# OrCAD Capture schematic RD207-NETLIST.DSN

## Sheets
1 8: size A3
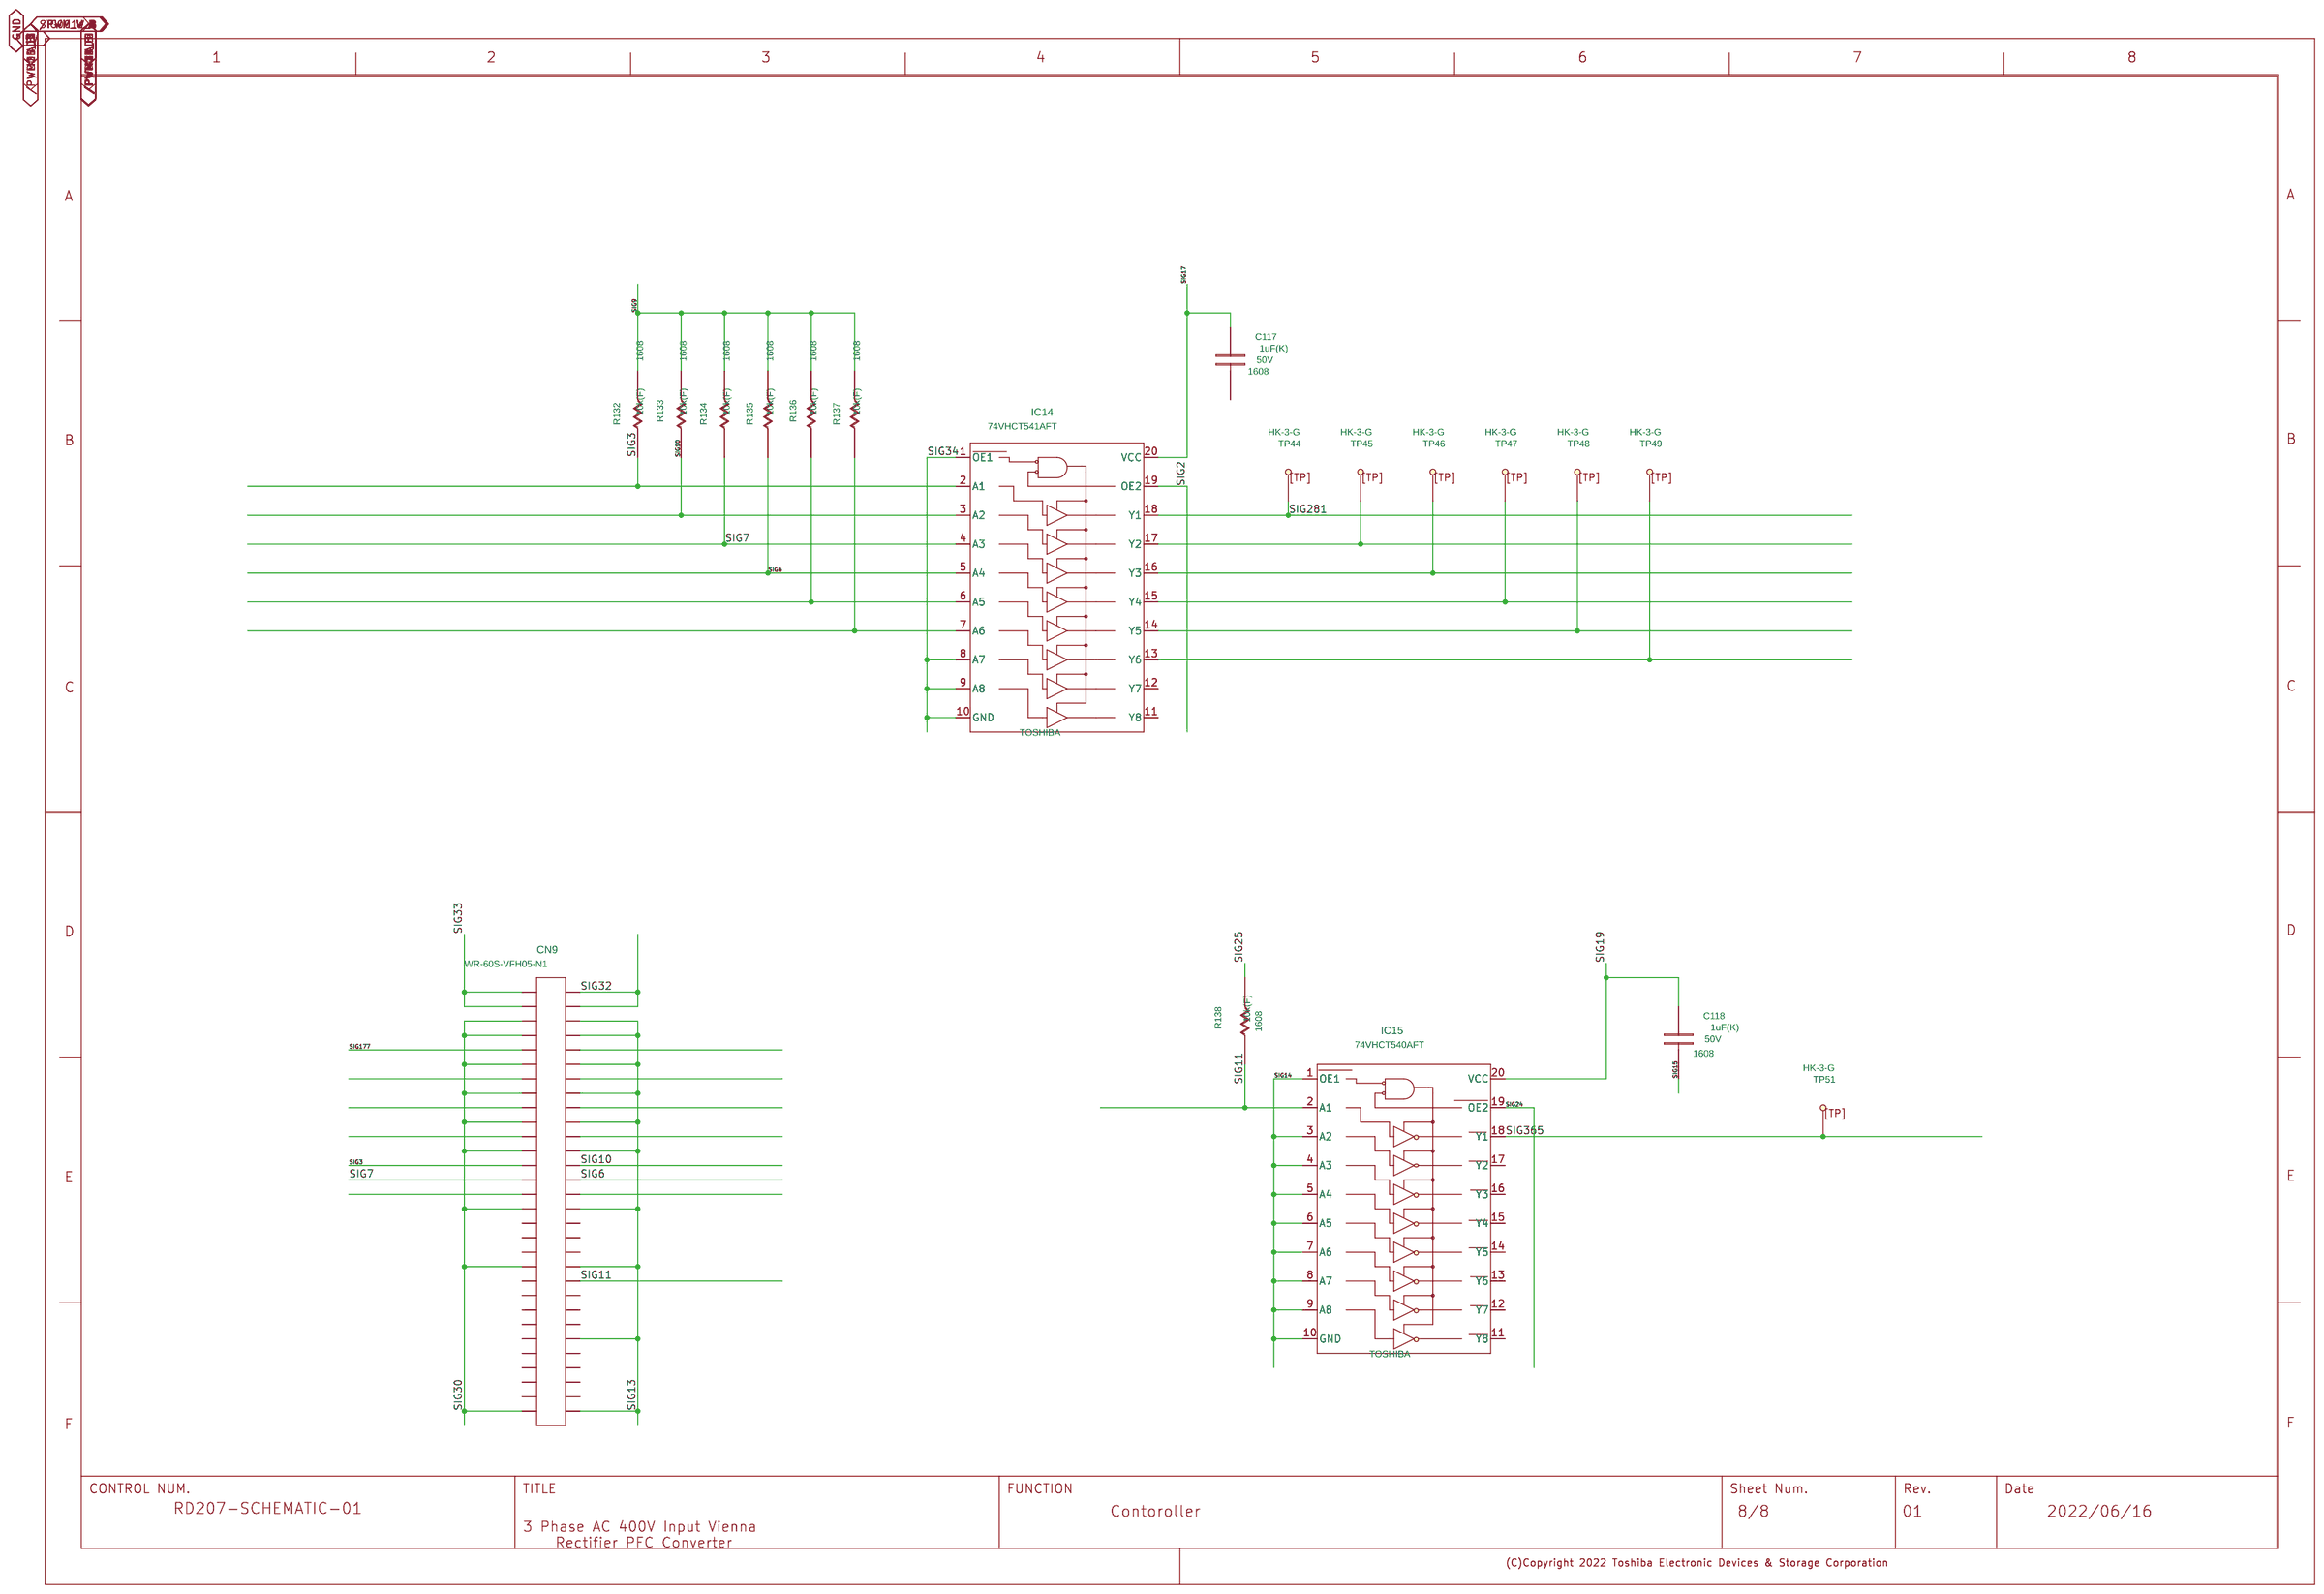
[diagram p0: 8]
2 7: size A3
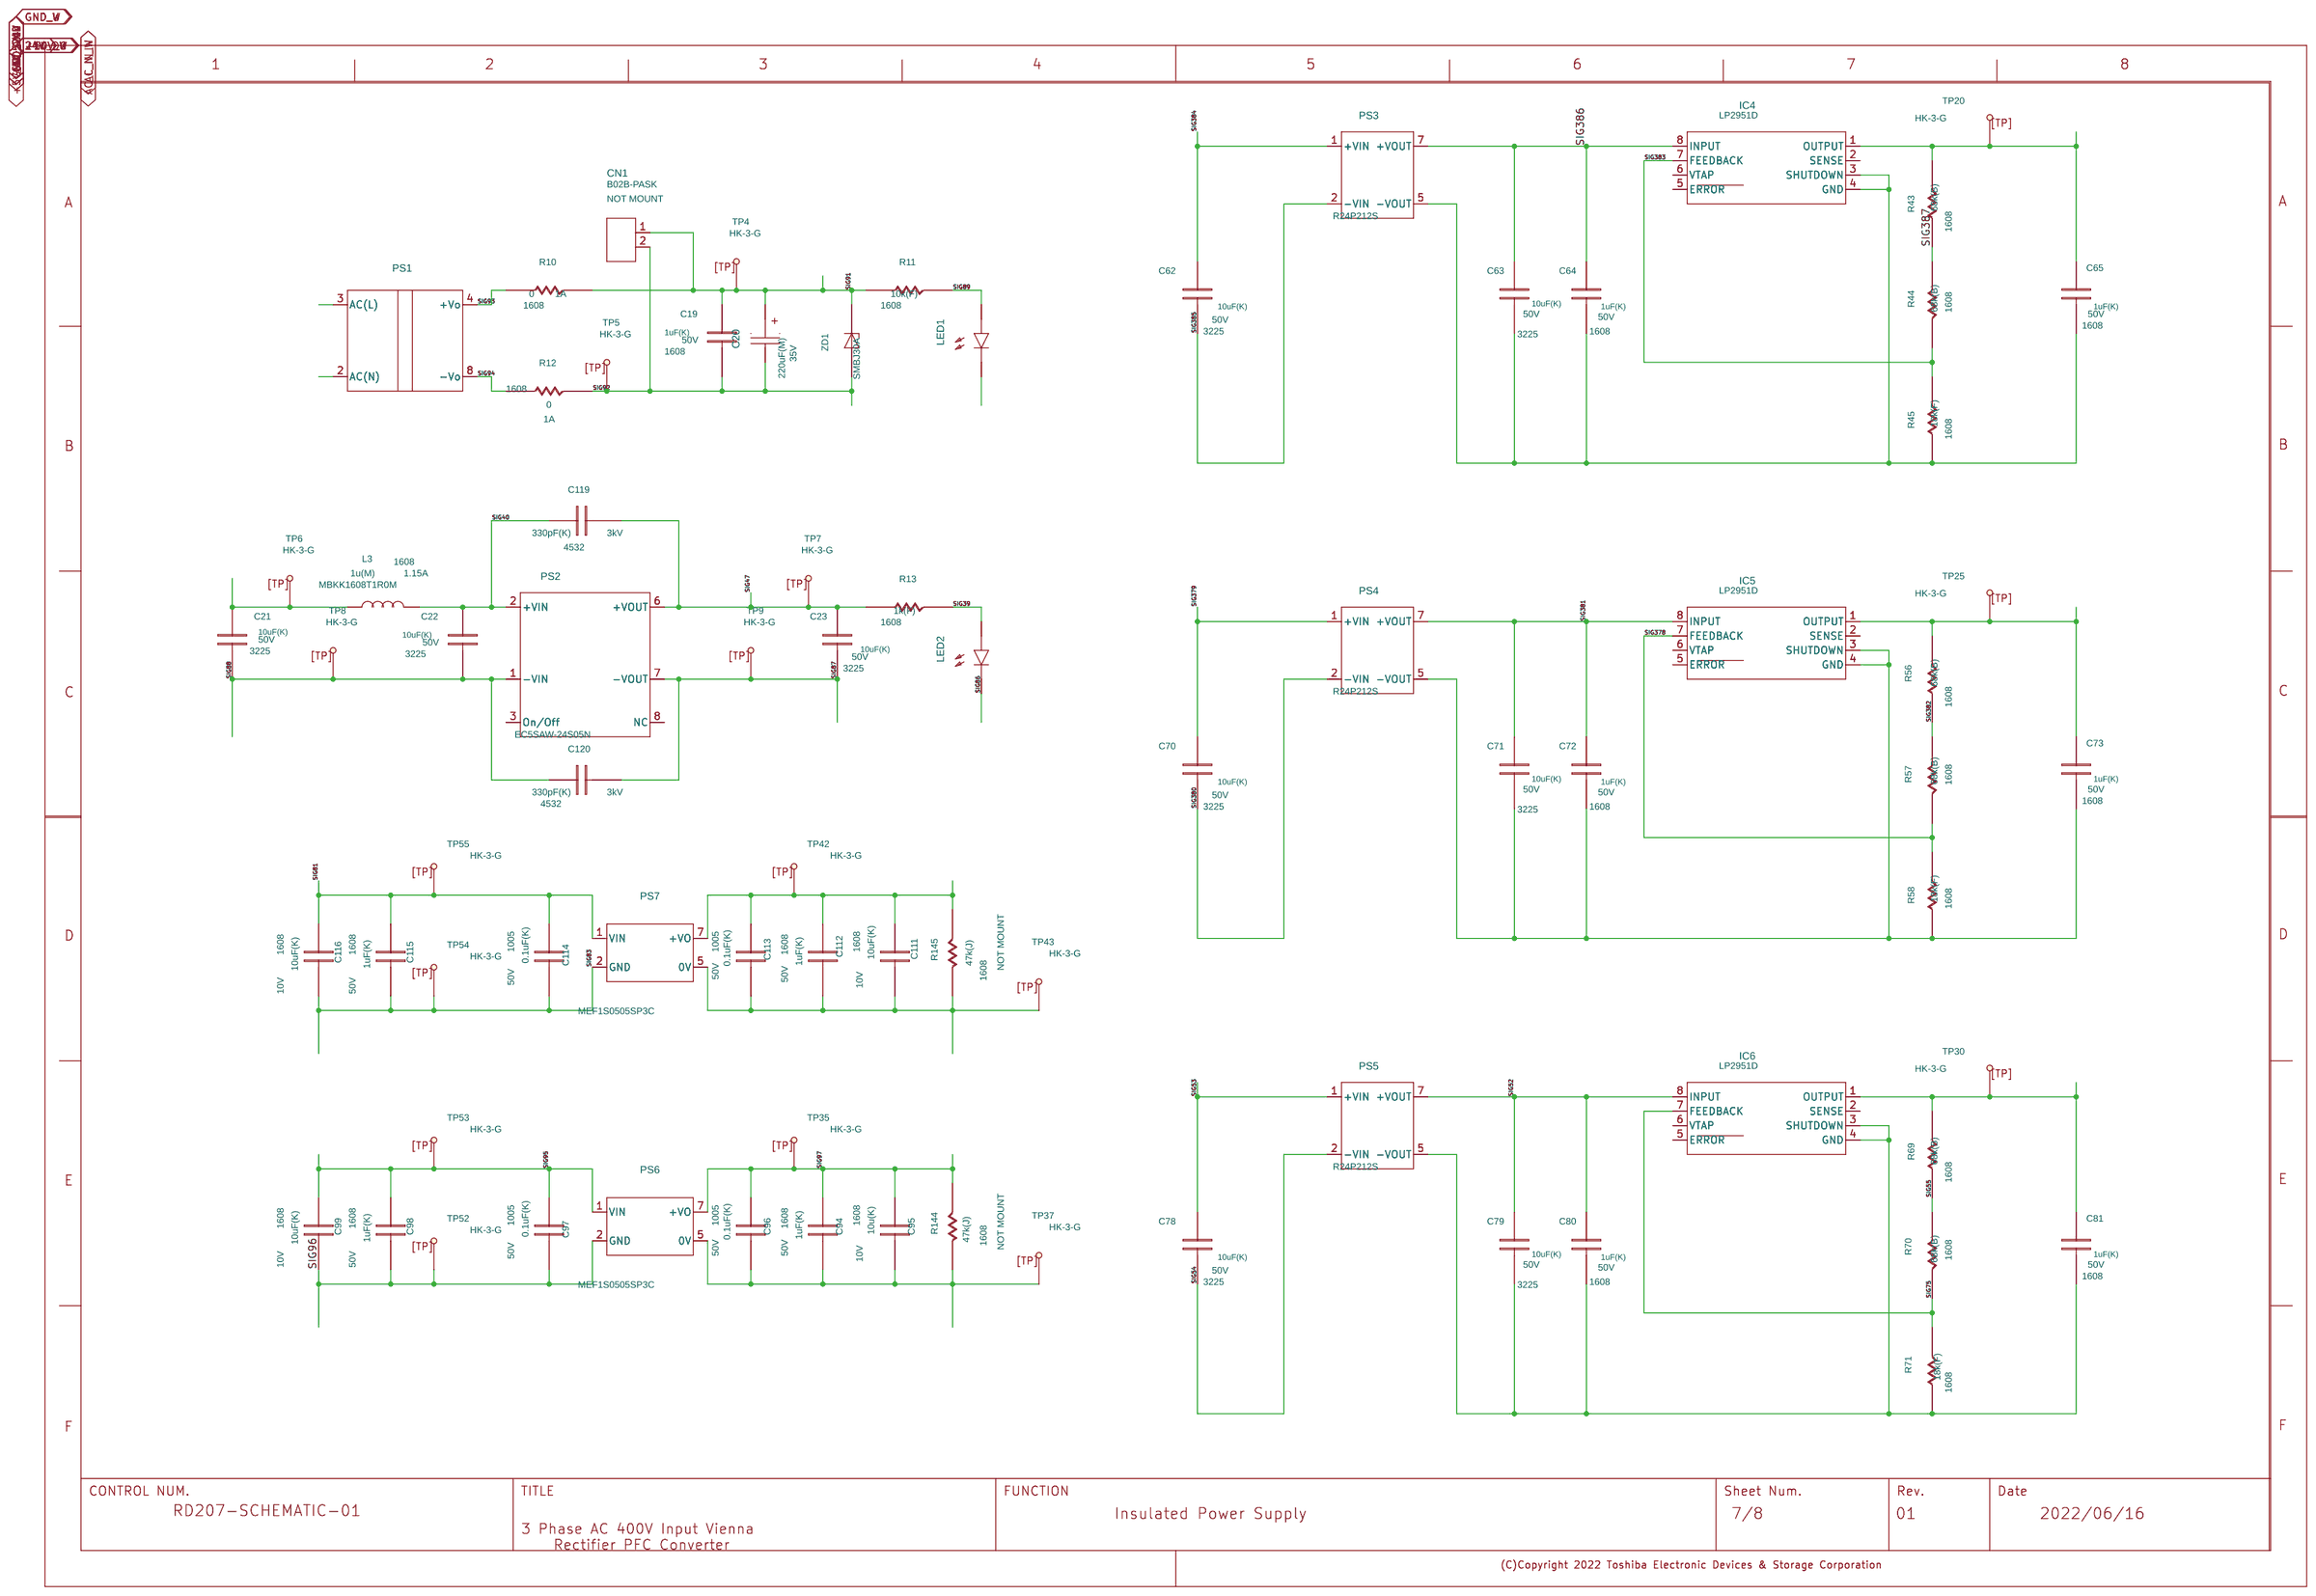
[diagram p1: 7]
3 6: size A3
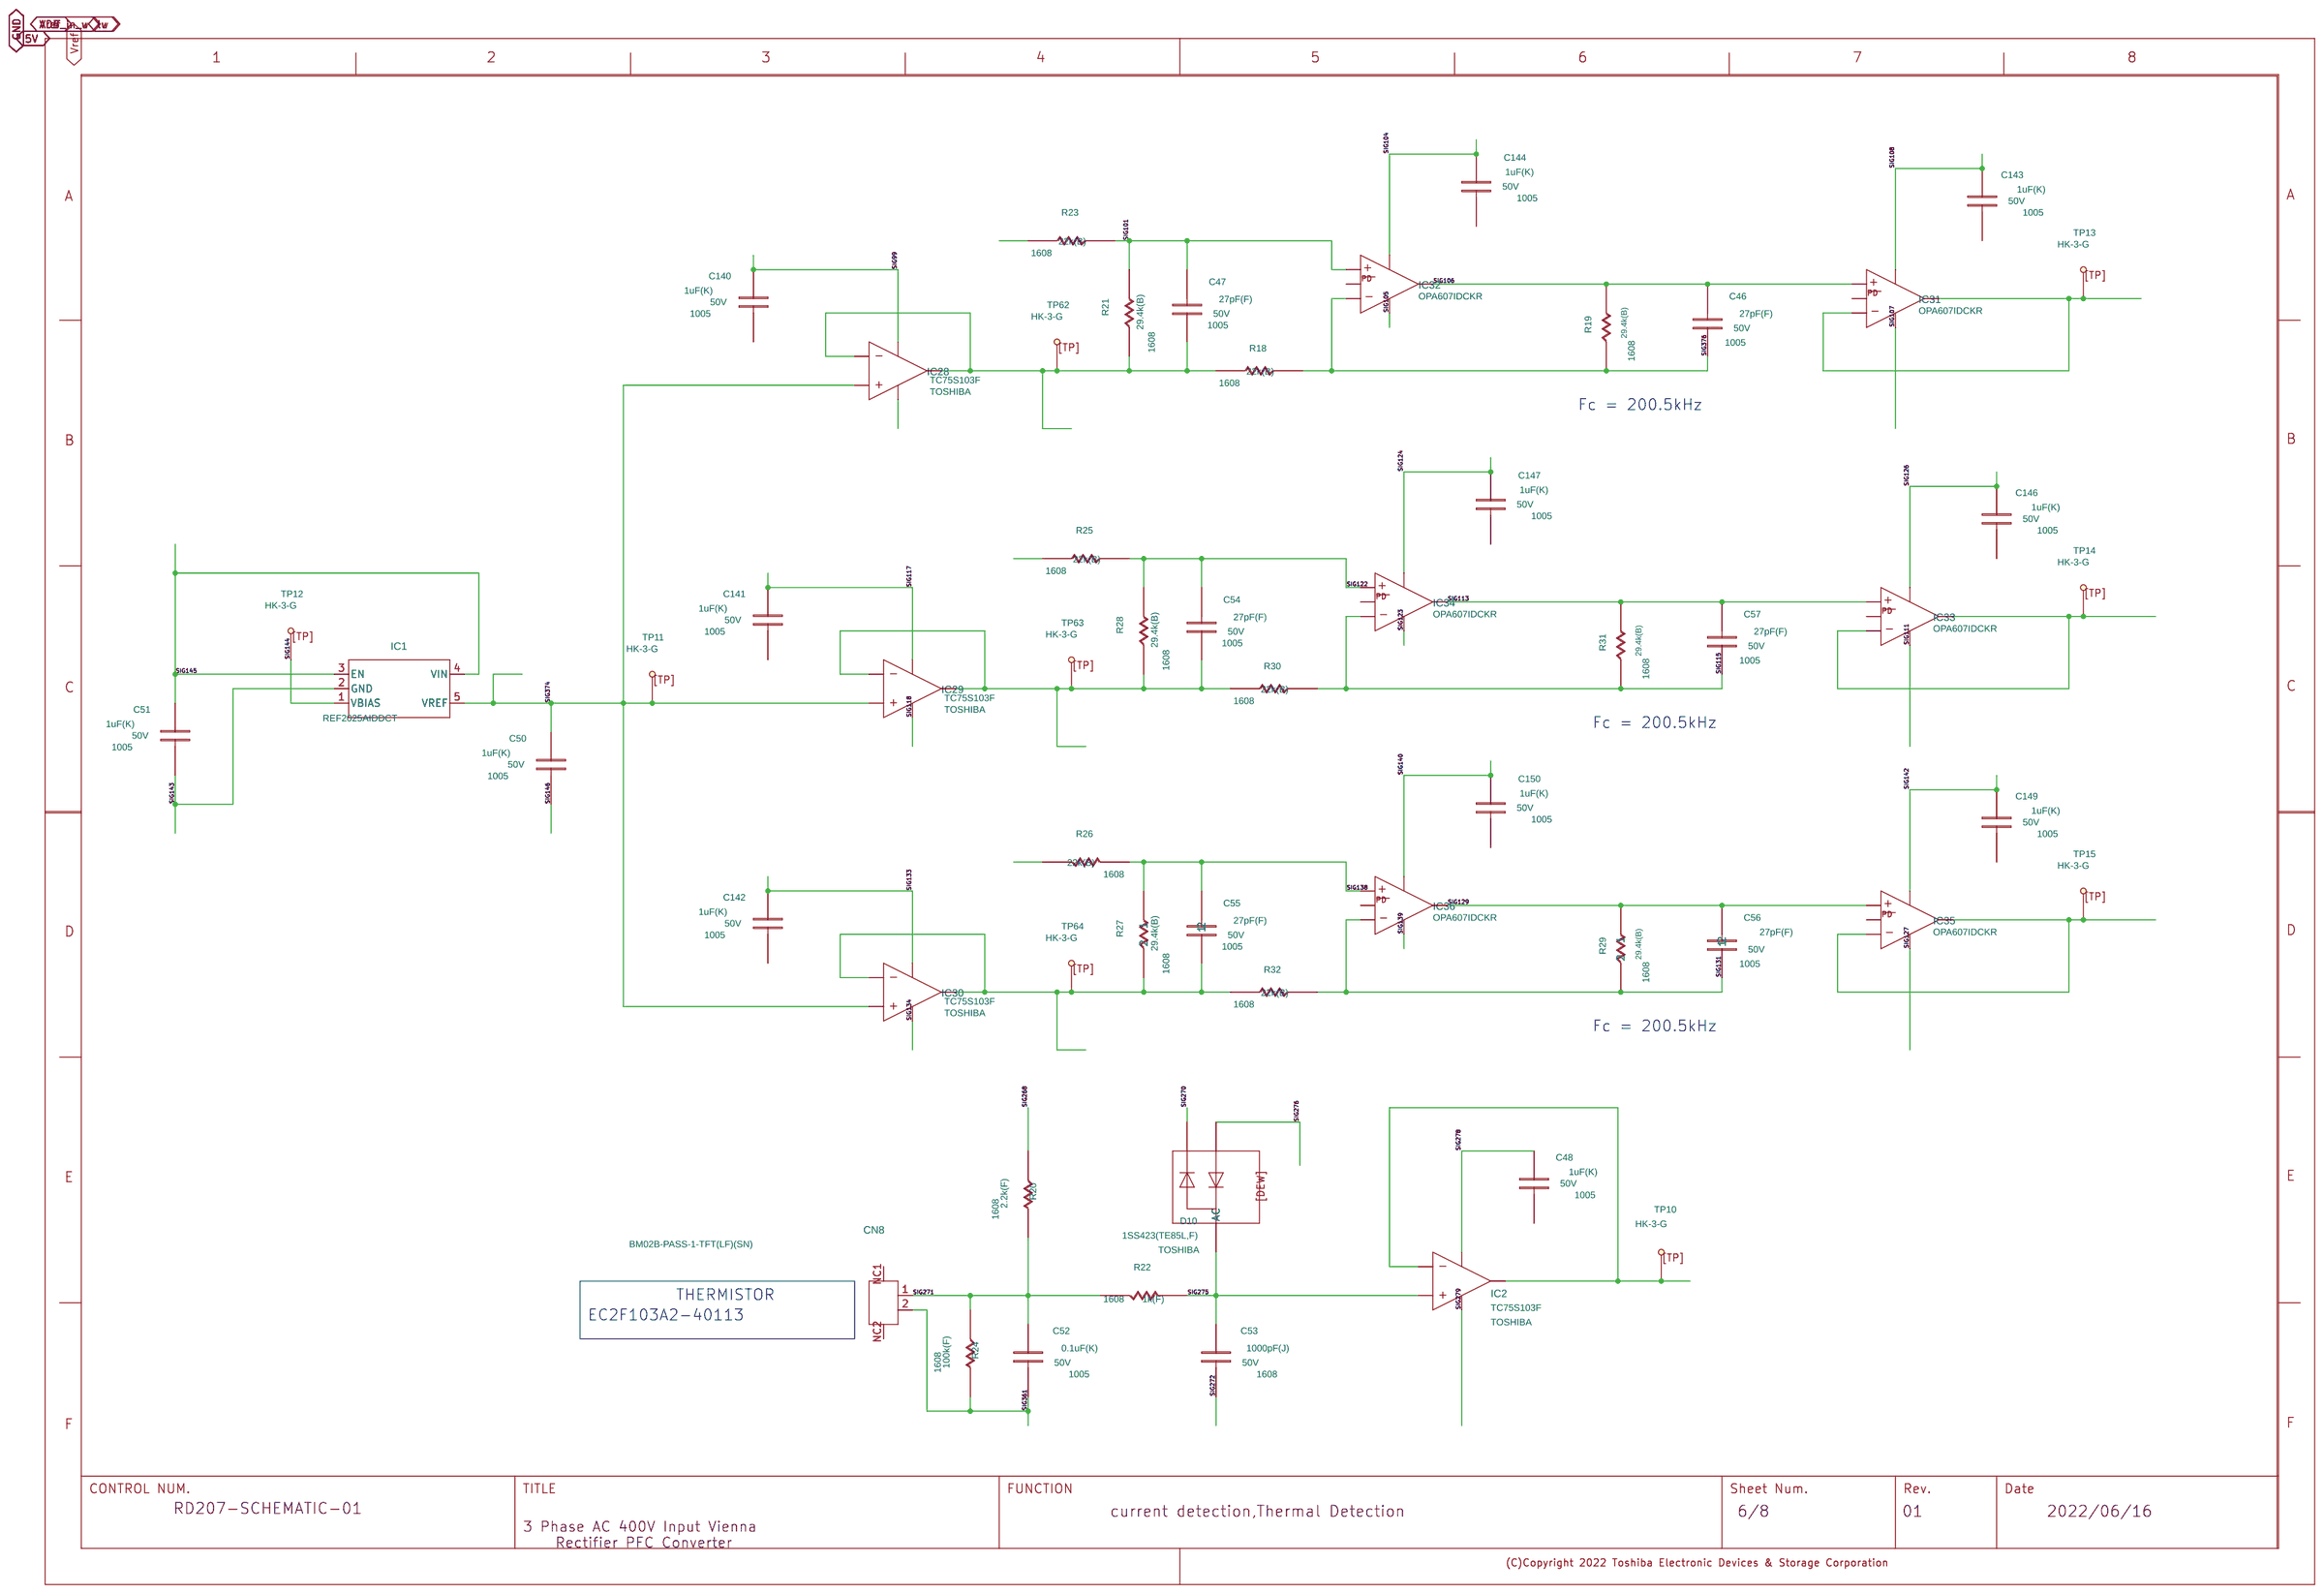
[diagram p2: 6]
4 5: size A3
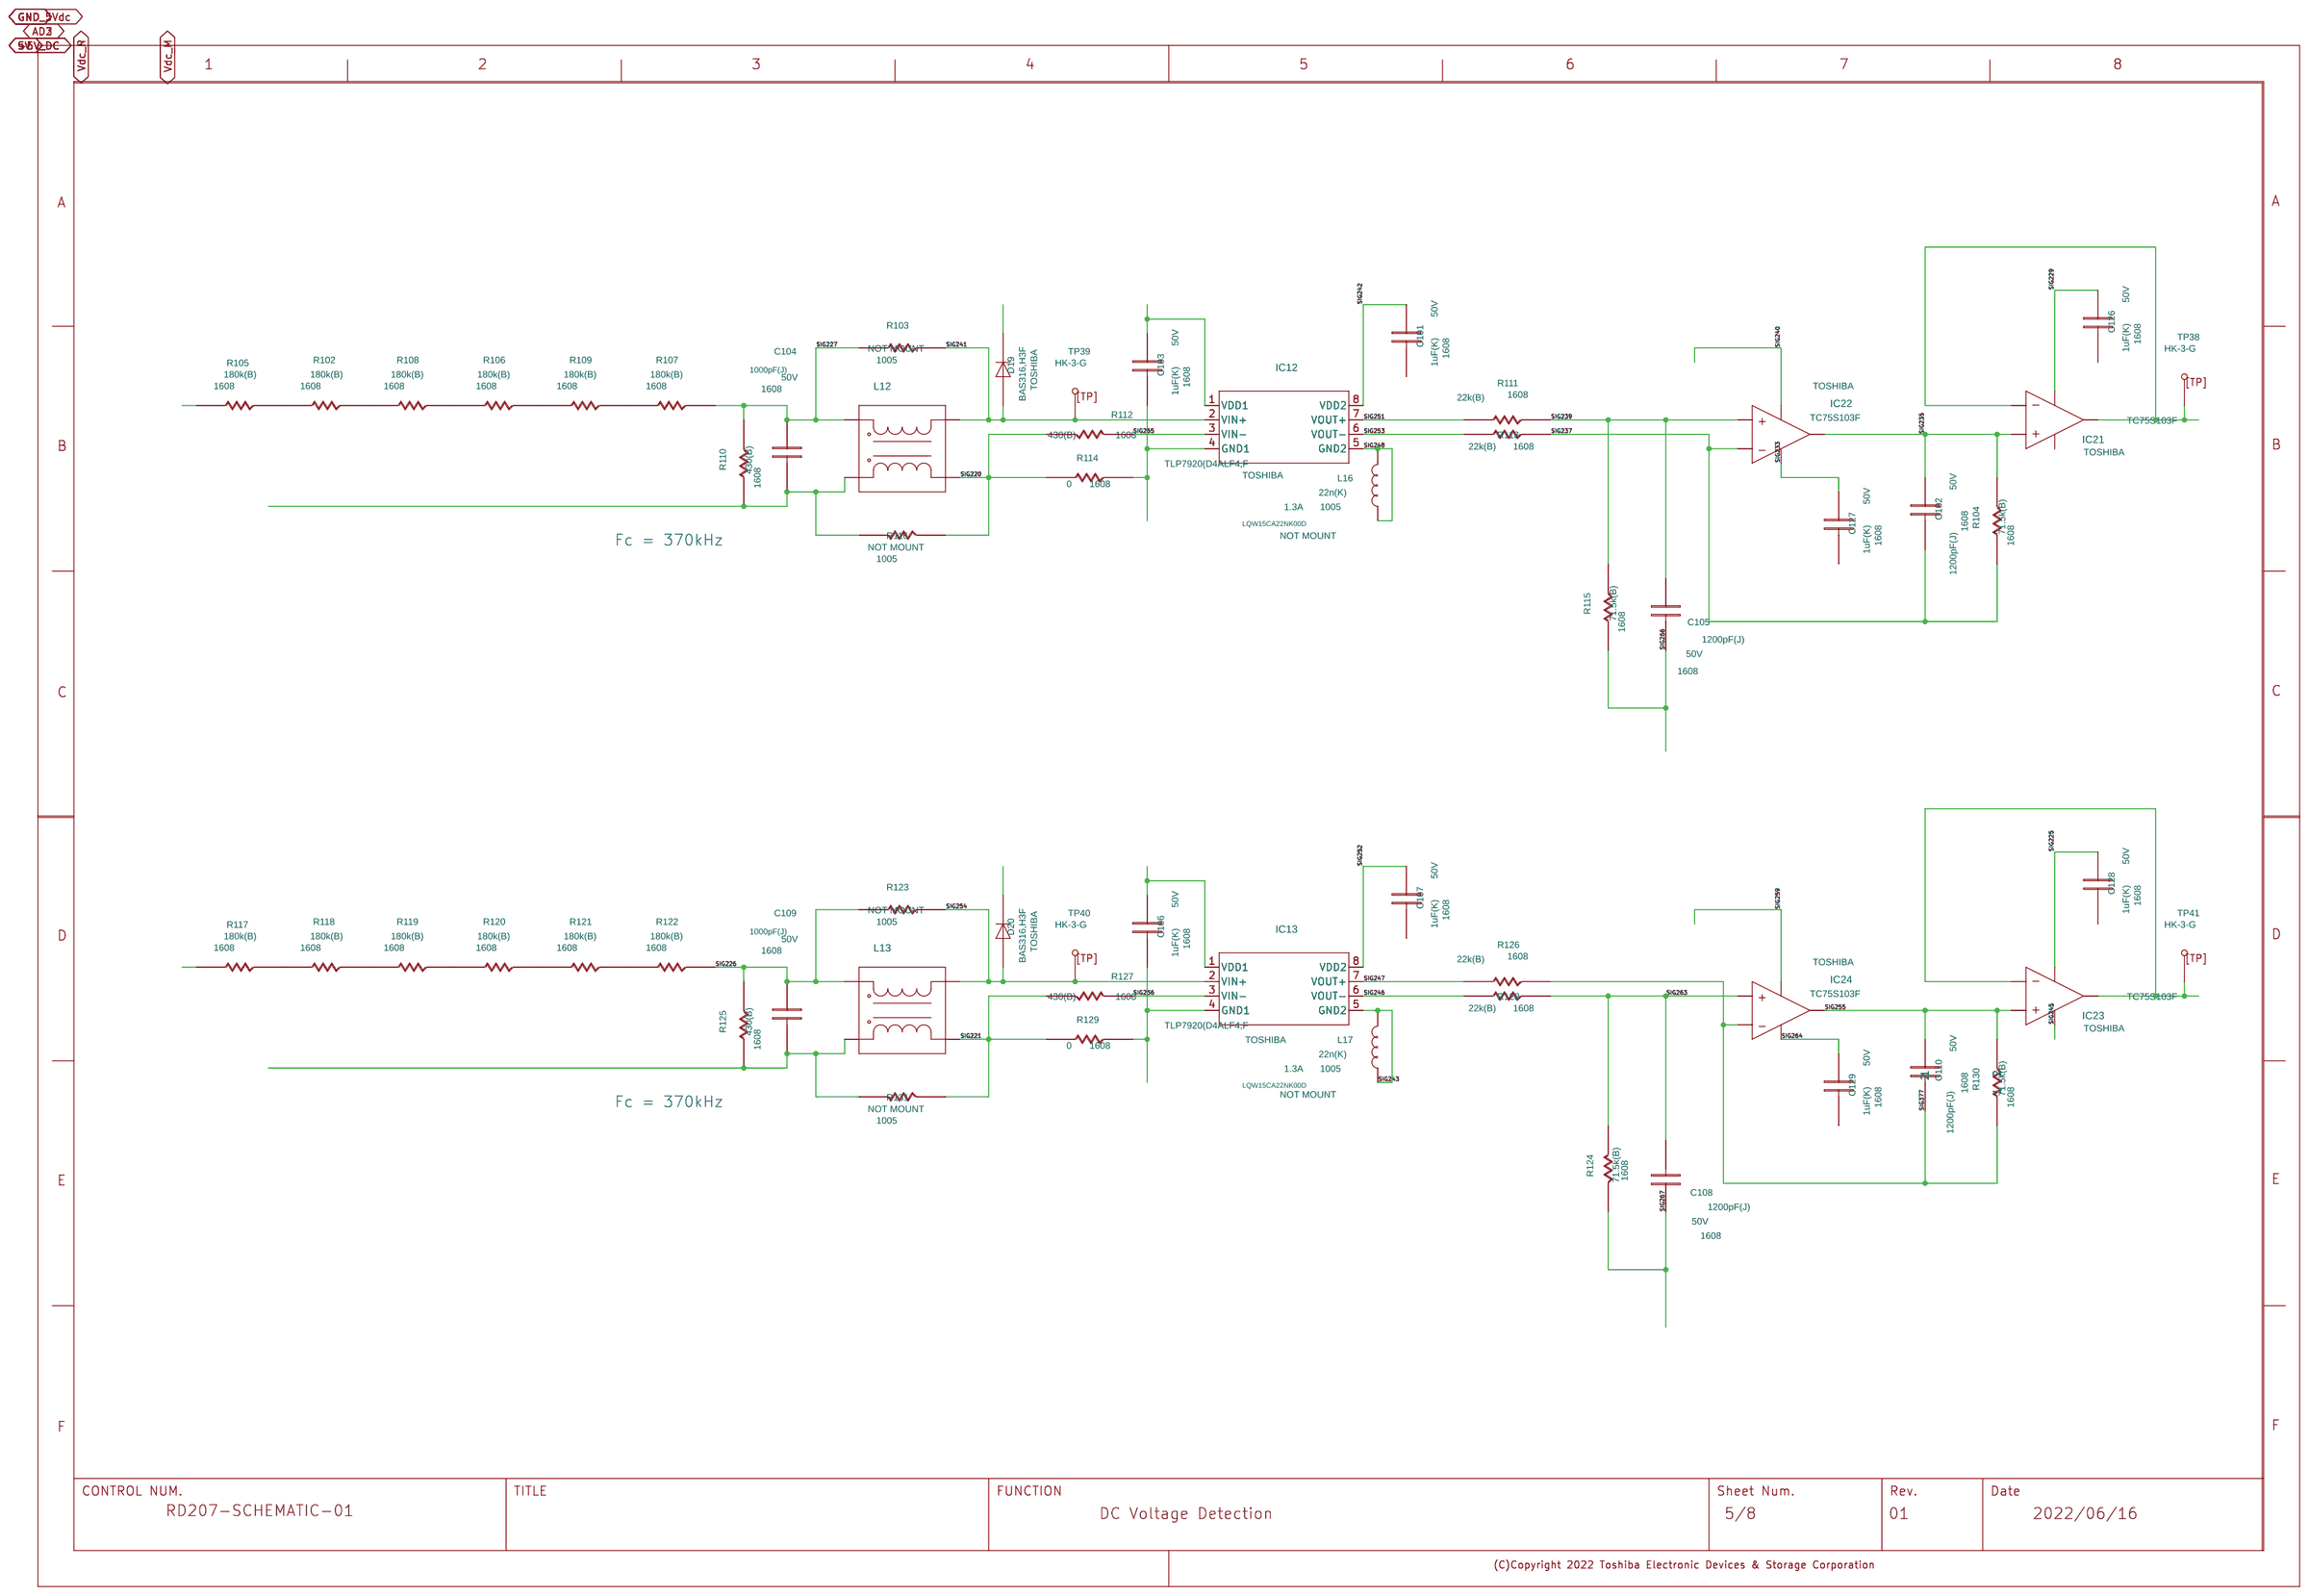
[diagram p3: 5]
5 4: size A3
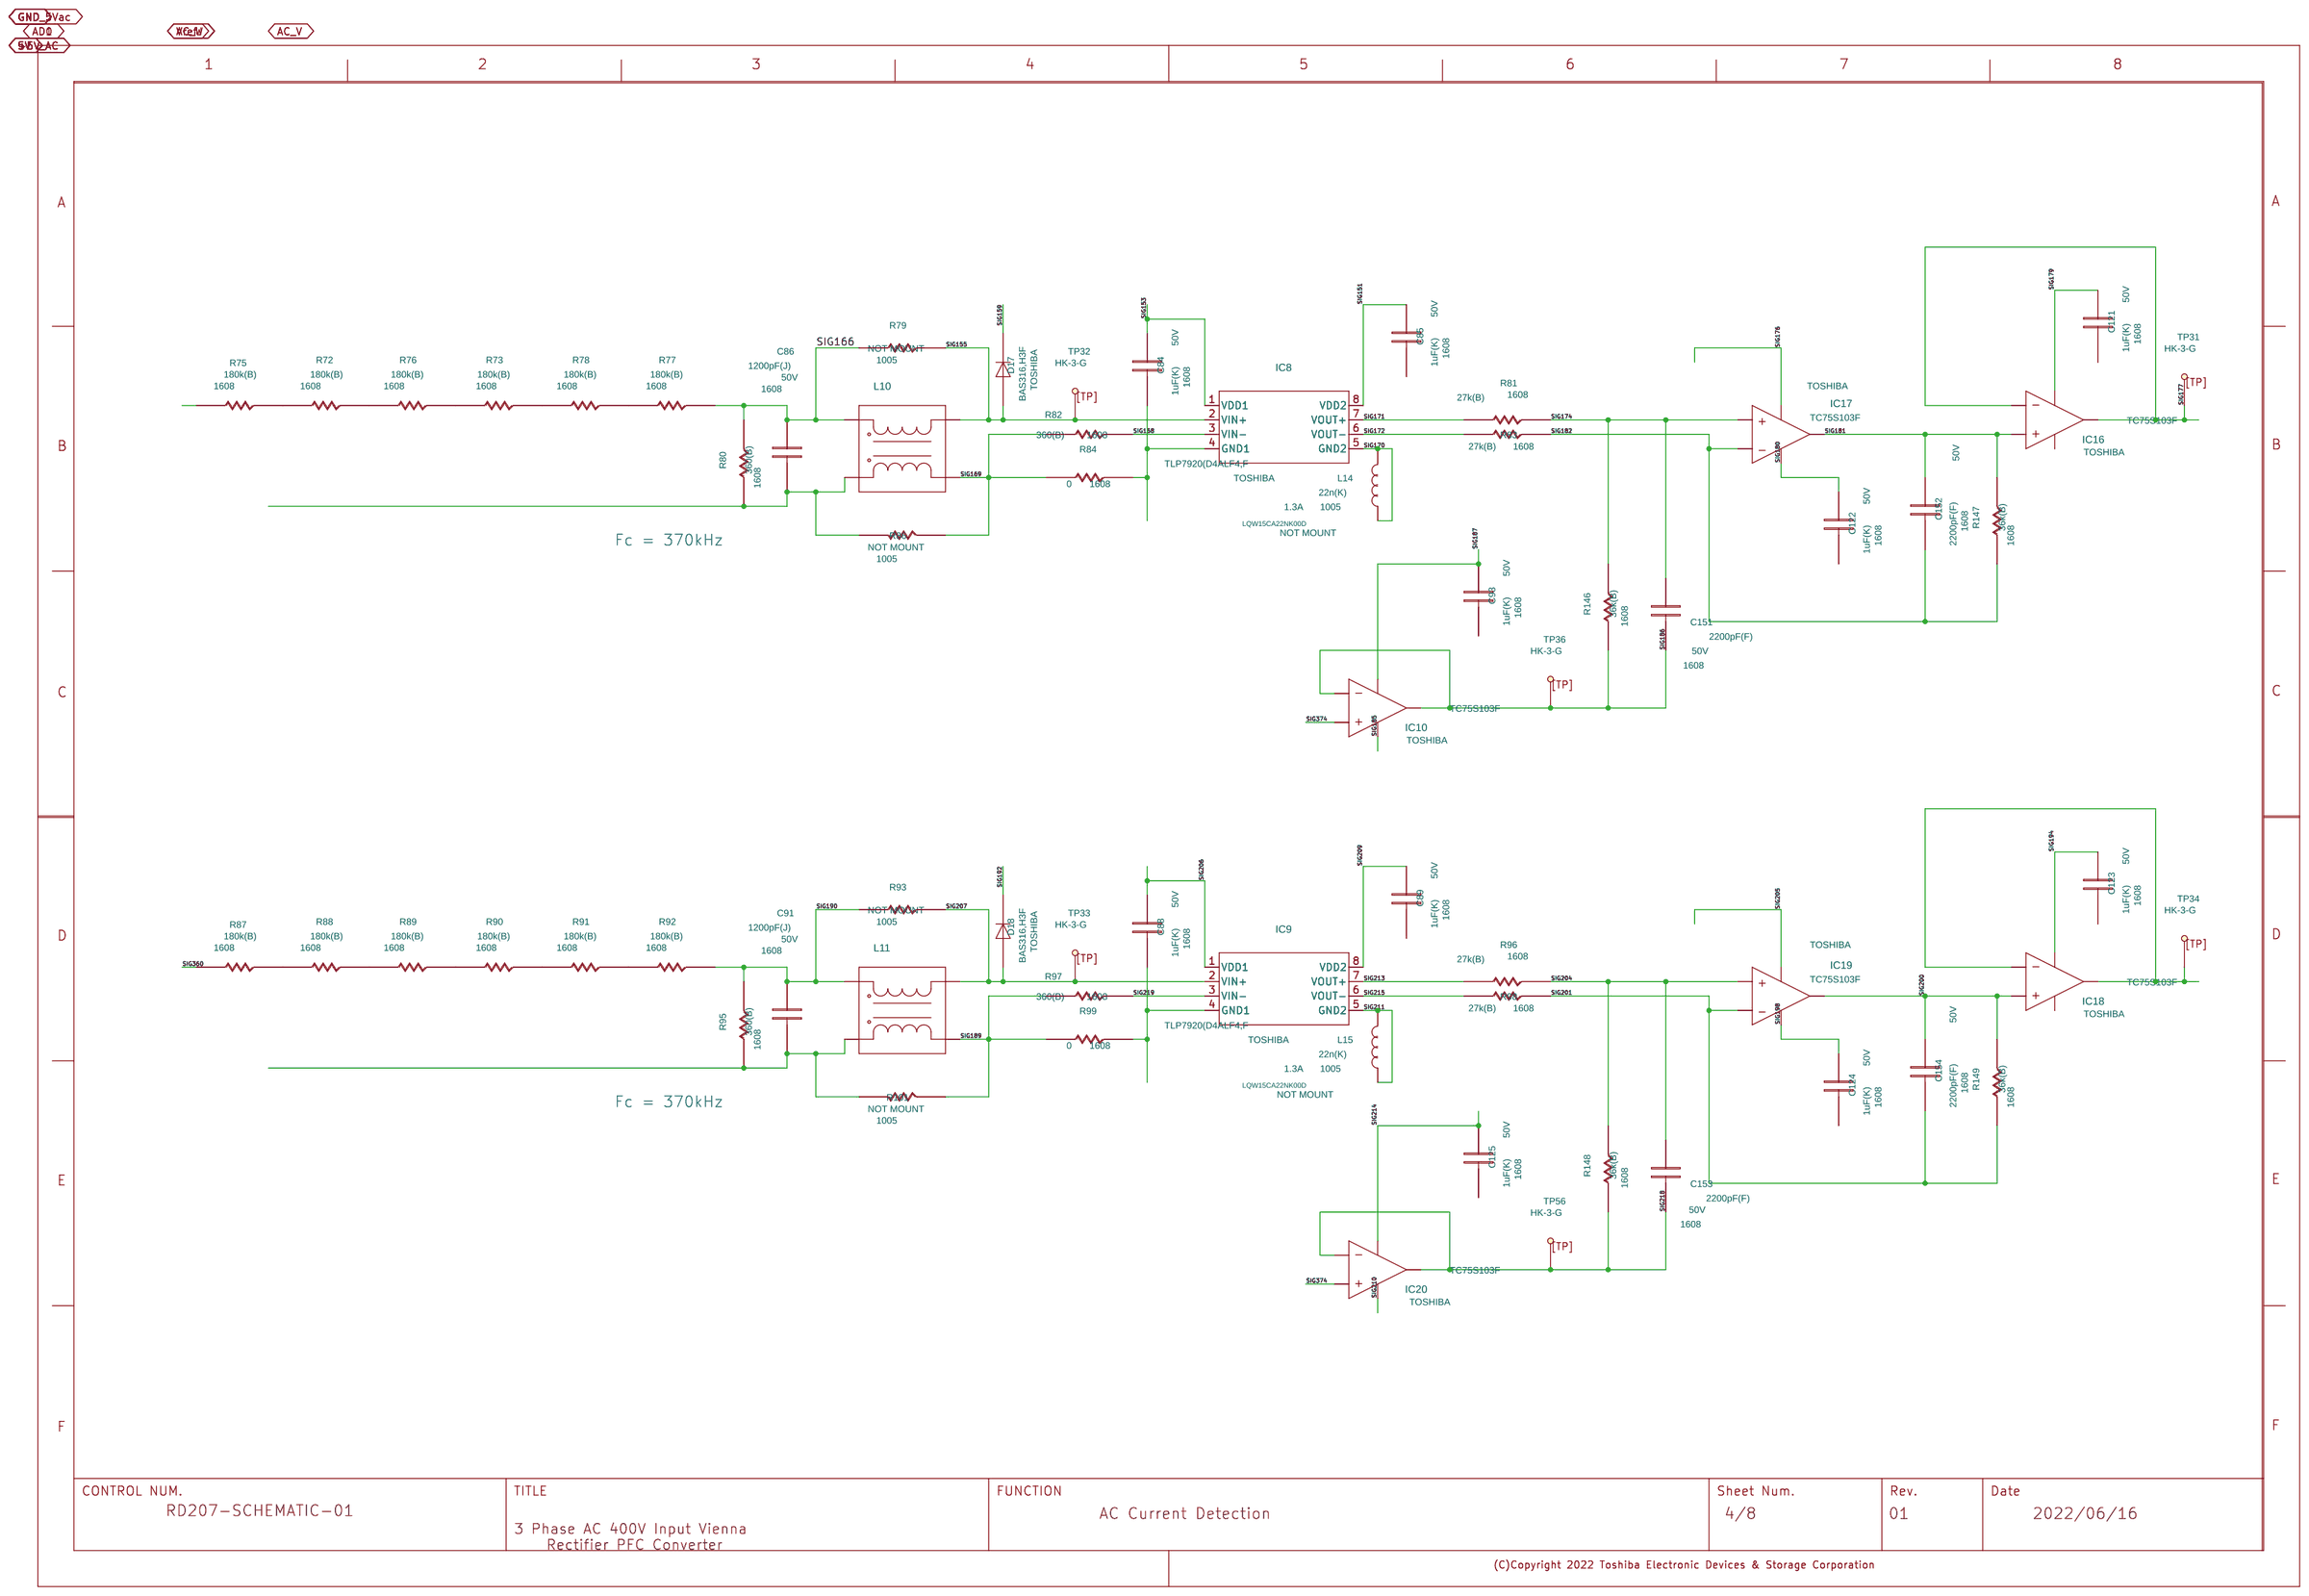
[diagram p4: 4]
6 3: size A3
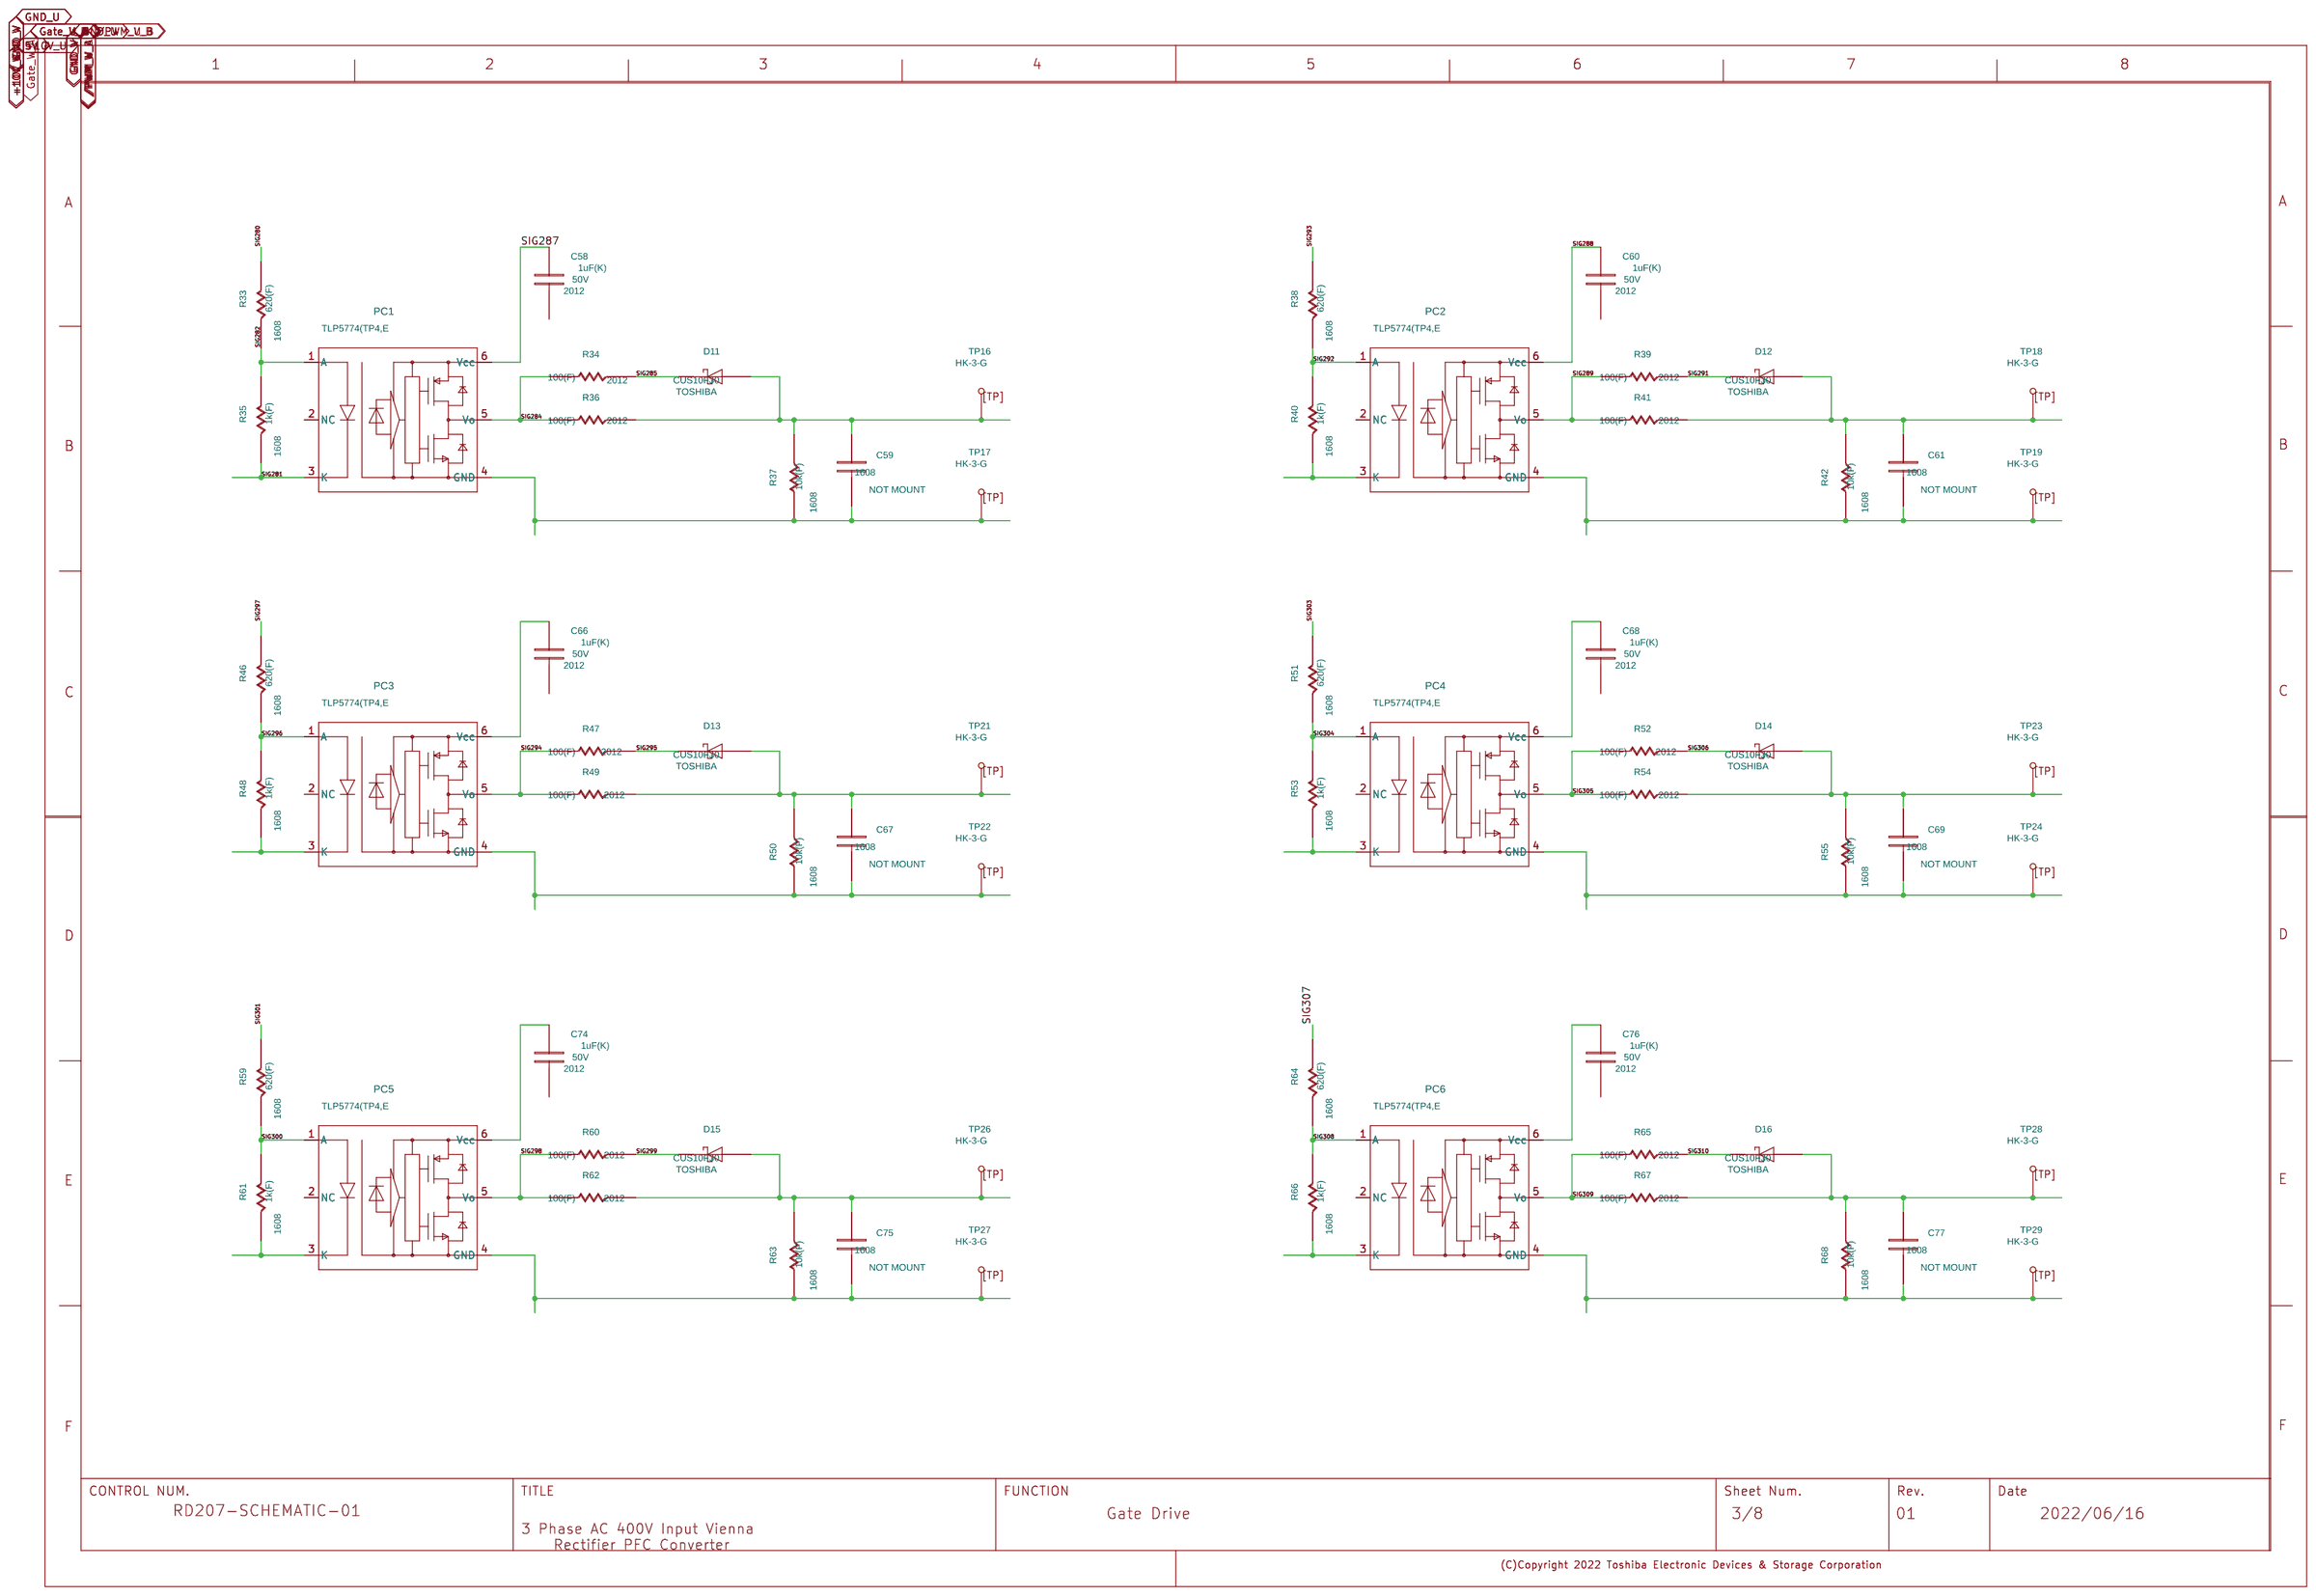
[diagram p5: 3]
7 2: size A3
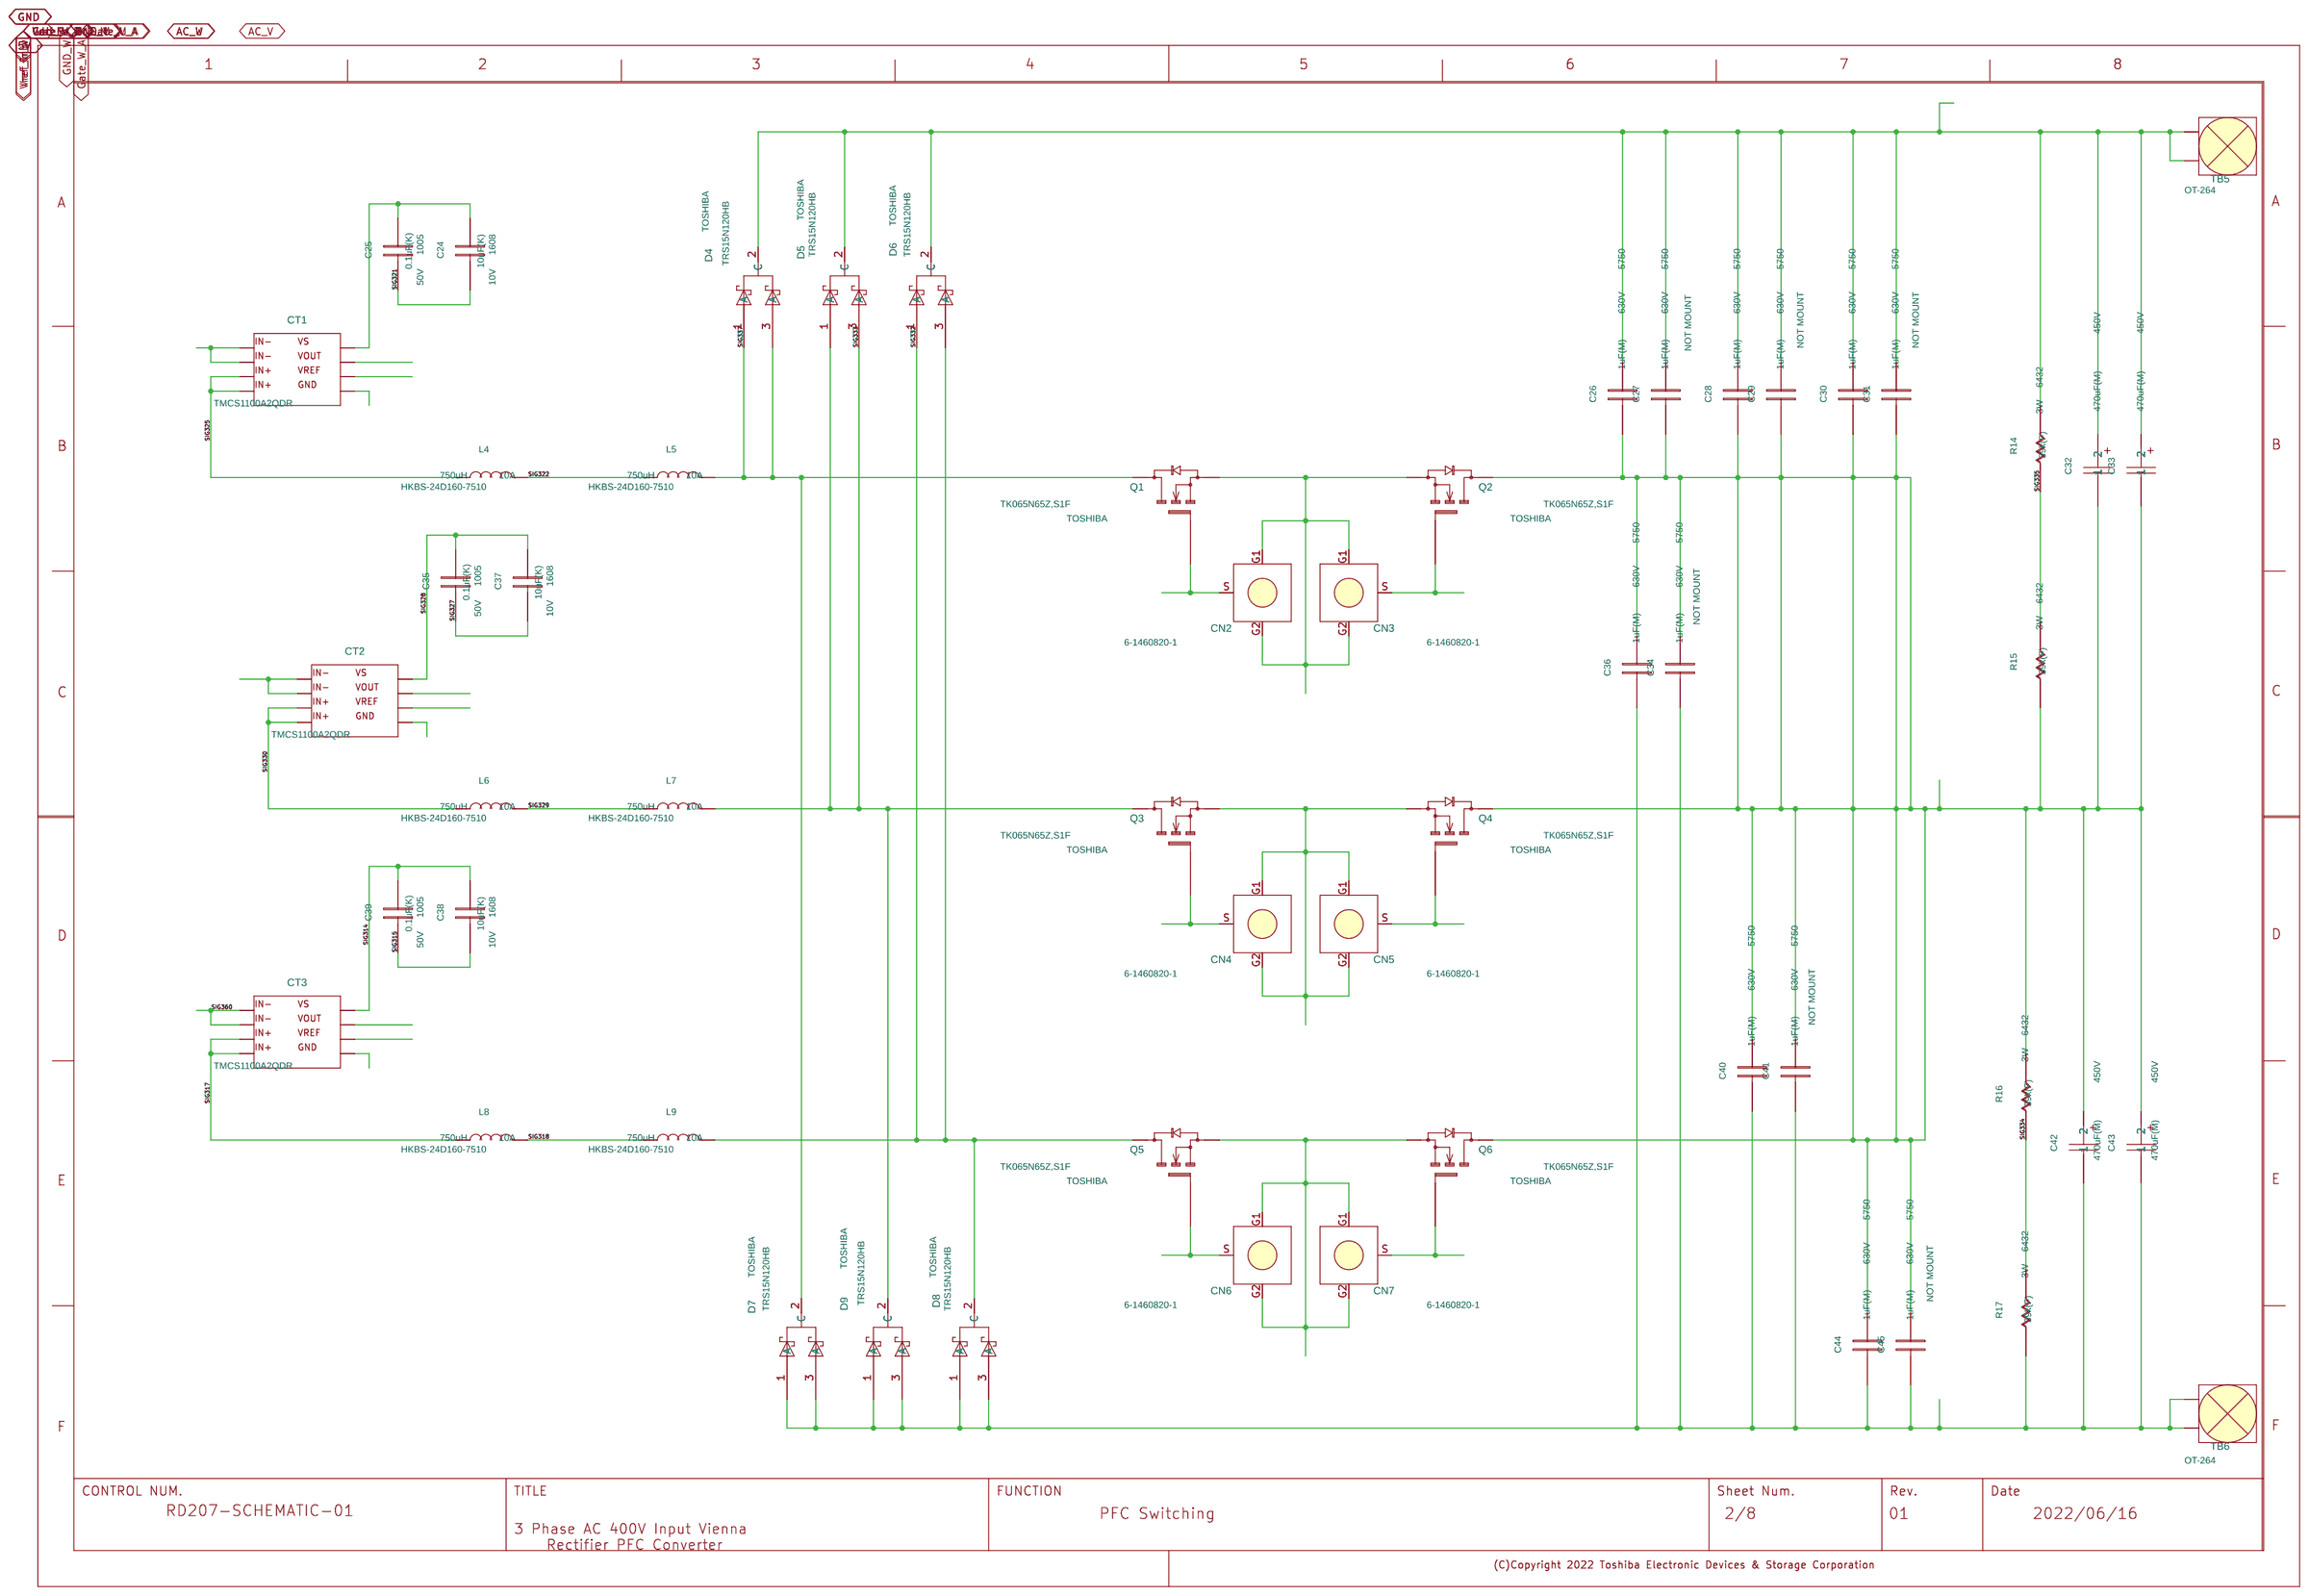
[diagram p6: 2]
8 1: size A3
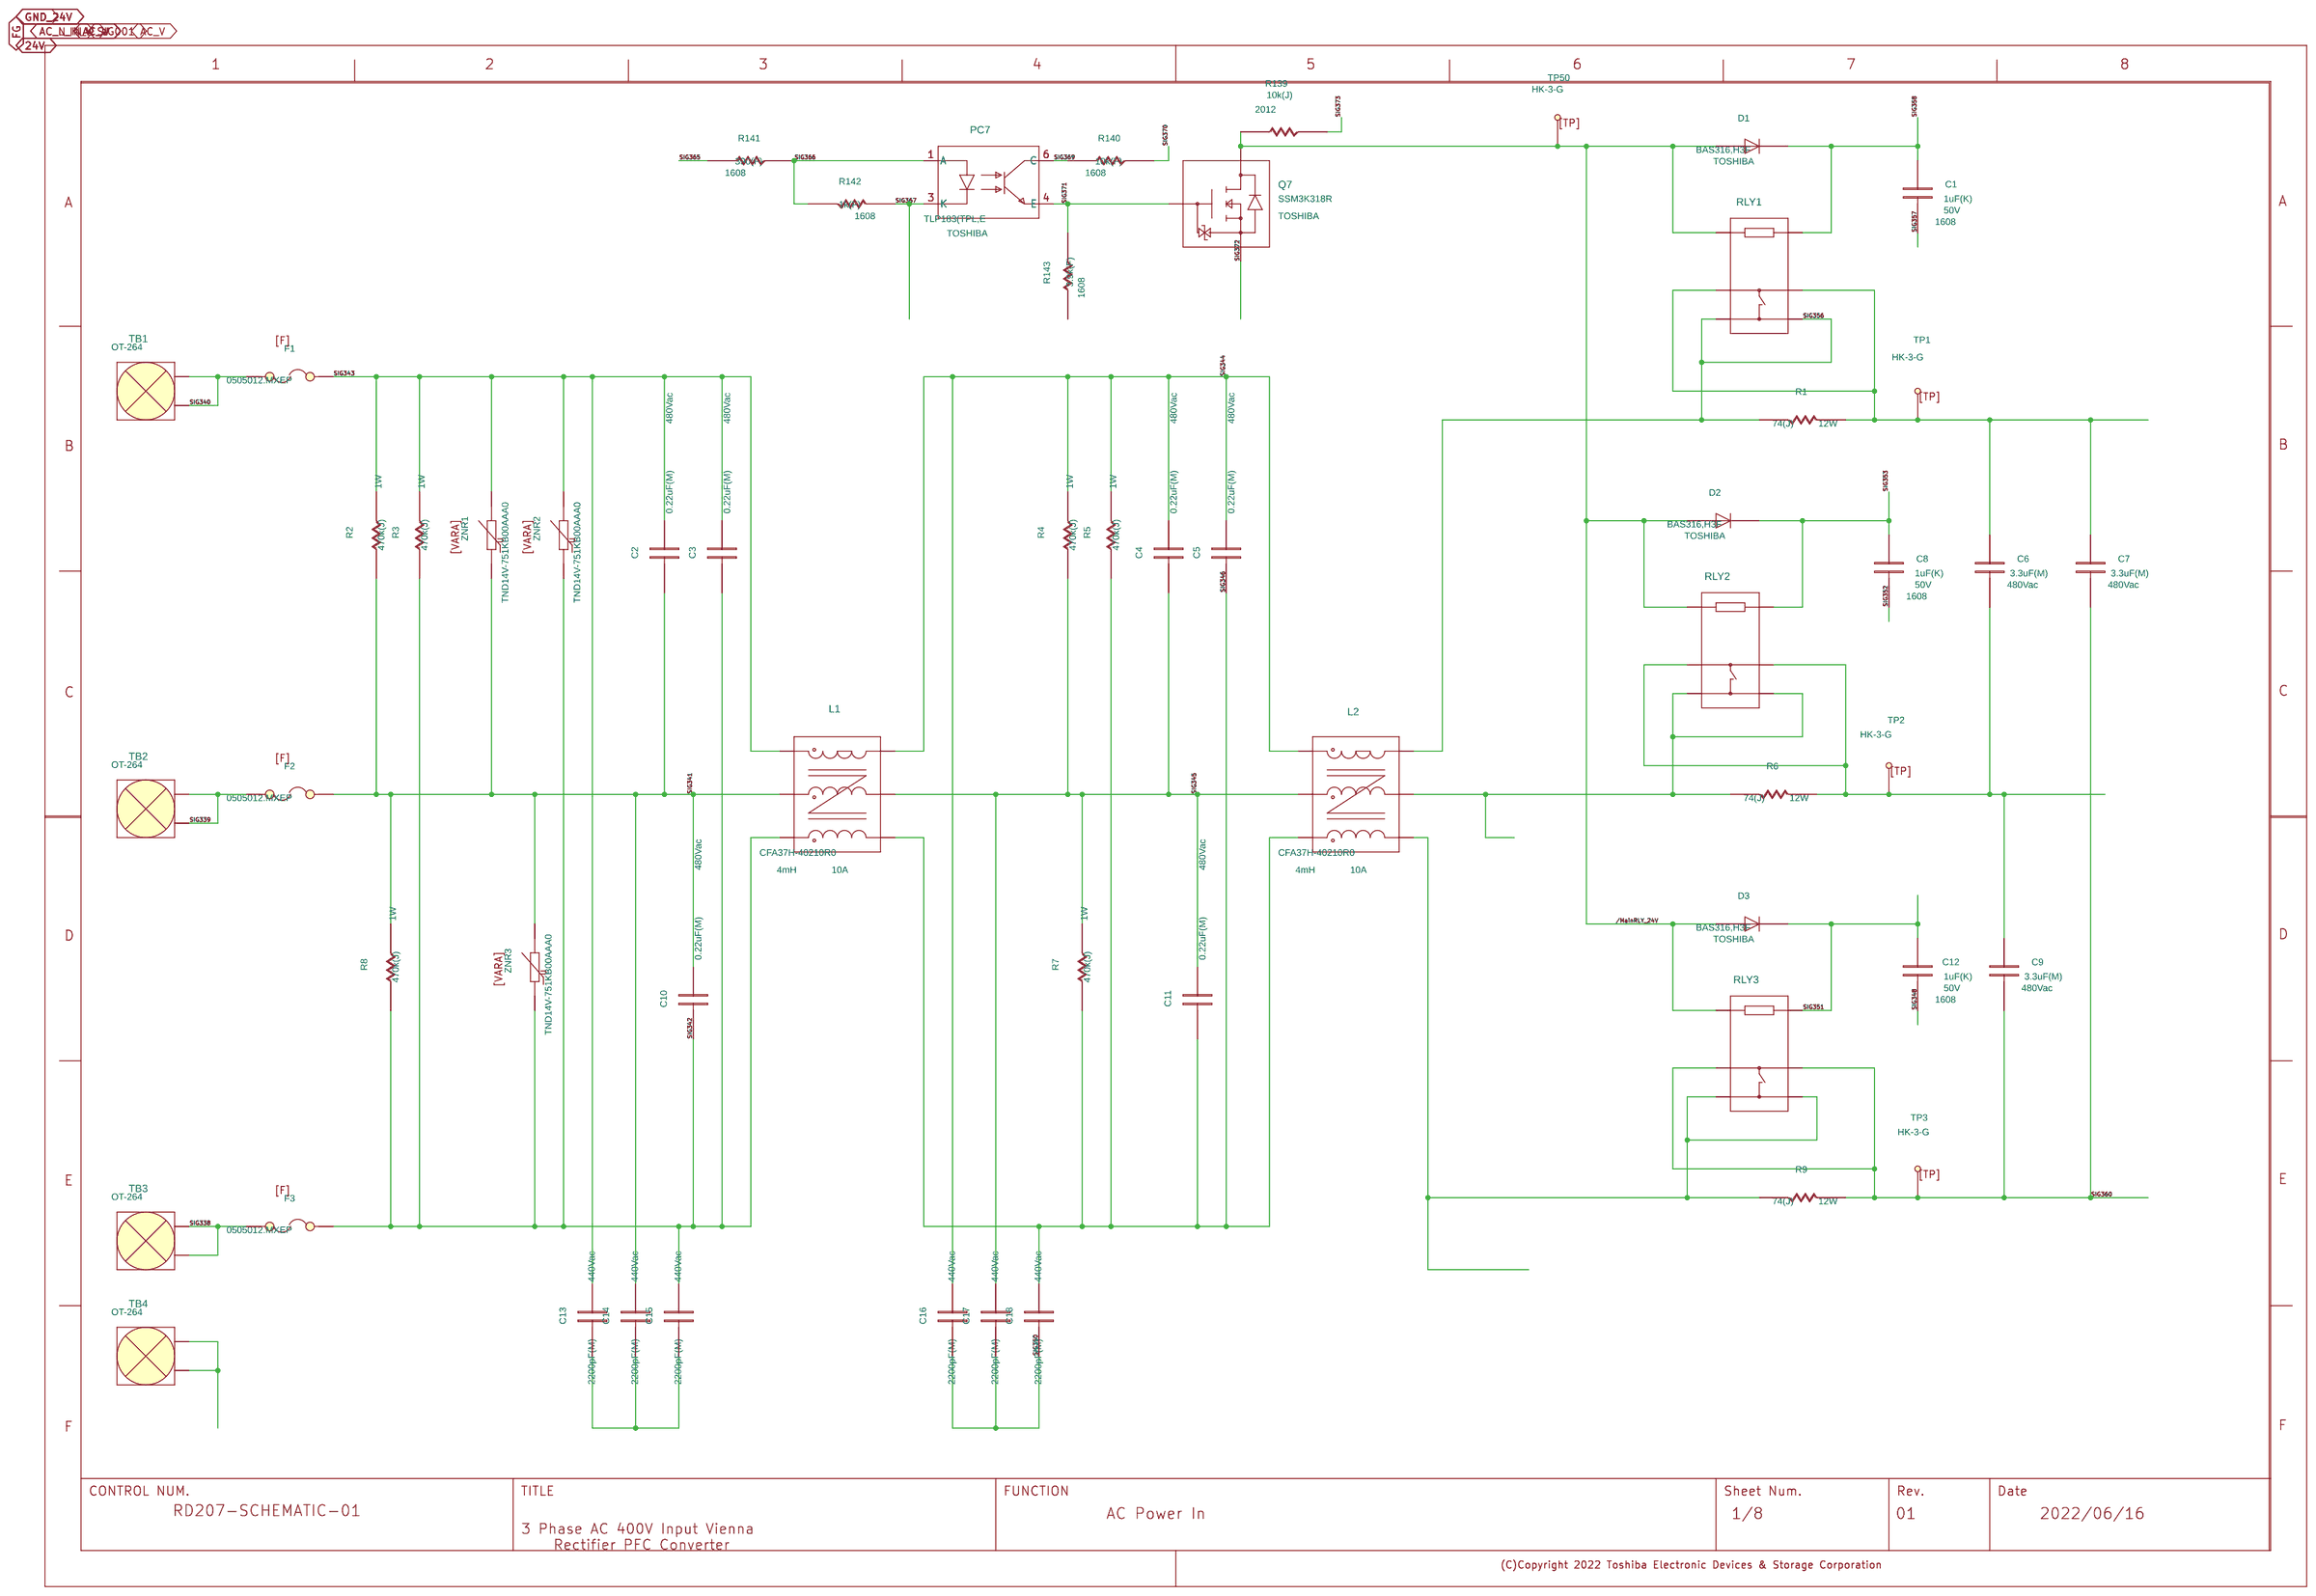
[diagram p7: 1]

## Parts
sheet 1
C1  C
C2  C
C3  C
C4  C
C5  C
C6  C
C7  C
C8  C
C9  C
C10  C
C11  C
C12  C
C13  C
C14  C
C15  C
C16  C
C17  C
C18  C
D1  D
D2  D
D3  D
F1  F
F2  F
F3  F
L1  CFA37H-40210R0
L2  CFA37H-40210R0
PC7  TLP183(TPL,E
Q7  SSM3K318R
R1  R
R2  R
R3  R
R4  R
R5  R
R6  R
R7  R
R8  R
R9  R
R139  R
R140  R
R141  R
R142  R
R143  R
RLY1  G2RL-1A4-E-CF DC24
RLY2  G2RL-1A4-E-CF DC24
RLY3  G2RL-1A4-E-CF DC24
TB1  OT-264
TB2  OT-264
TB3  OT-264
TB4  OT-264
TP1  TP
TP2  TP
TP3  TP
TP50  TP
U?#7  WAKU_DEF100
ZNR1  VARA
ZNR2  VARA
ZNR3  VARA
sheet 2
C24  C
C25  C
C26  C
C27  C
C28  C
C29  C
C30  C
C31  C
C32  CP
C33  CP
C34  C
C35  C
C36  C
C37  C
C38  C
C39  C
C40  C
C41  C
C42  CP
C43  CP
C44  C
C45  C
CN2  6-1460820-1
CN3  6-1460820-1
CN4  6-1460820-1
CN5  6-1460820-1
CN6  6-1460820-1
CN7  6-1460820-1
CT1  TMCS1100A2QDR
CT2  TMCS1100A2QDR
CT3  TMCS1100A2QDR
D4  TRS15N120HB
D5  TRS15N120HB
D6  TRS15N120HB
D7  TRS15N120HB
D8  TRS15N120HB
D9  TRS15N120HB
L4  L
L5  L
L6  L
L7  L
L8  L
L9  L
Q1  TK065N65Z,S1F
Q2  TK065N65Z,S1F
Q3  TK065N65Z,S1F
Q4  TK065N65Z,S1F
Q5  TK065N65Z,S1F
Q6  TK065N65Z,S1F
R14  R
R15  R
R16  R
R17  R
TB5  OT-264
TB6  OT-264
U?#6  WAKU_DEF100
sheet 3
C58  C
C59  C
C60  C
C61  C
C66  C
C67  C
C68  C
C69  C
C74  C
C75  C
C76  C
C77  C
D11  SBD
D12  SBD
D13  SBD
D14  SBD
D15  SBD
D16  SBD
PC1  TLP5774
PC2  TLP5774
PC3  TLP5774
PC4  TLP5774
PC5  TLP5774
PC6  TLP5774
R33  R
R34  R
R35  R
R36  R
R37  R
R38  R
R39  R
R40  R
R41  R
R42  R
R46  R
R47  R
R48  R
R49  R
R50  R
R51  R
R52  R
R53  R
R54  R
R55  R
R59  R
R60  R
R61  R
R62  R
R63  R
R64  R
R65  R
R66  R
R67  R
R68  R
TP16  TP
TP17  TP
TP18  TP
TP19  TP
TP21  TP
TP22  TP
TP23  TP
TP24  TP
TP26  TP
TP27  TP
TP28  TP
TP29  TP
U?#5  WAKU_DEF100
sheet 4
C84  C
C85  C
C86  C
C88  C
C89  C
C91  C
C93  C
C121  C
C122  C
C123  C
C124  C
C125  C
C151  C
C152  C
C153  C
C154  C
D17  D
D18  D
IC8  TLP7920(D4ALF1,F
IC9  TLP7920(D4ALF1,F
IC10  TC75S103F
IC16  TC75S103F
IC17  TC75S103F
IC18  TC75S103F
IC19  TC75S103F
IC20  TC75S103F
L10  ACT1210-101-2P-TL00
L11  ACT1210-101-2P-TL00
L14  L
L15  L
R72  R
R73  R
R75  R
R76  R
R77  R
R78  R
R79  R
R80  R
R81  R
R82  R
R83  R
R84  R
R86  R
R87  R
R88  R
R89  R
R90  R
R91  R
R92  R
R93  R
R95  R
R96  R
R97  R
R98  R
R99  R
R101  R
R146  R
R147  R
R148  R
R149  R
TP31  TP
TP32  TP
TP33  TP
TP34  TP
TP36  TP
TP56  TP
U?#4  WAKU_DEF100
sheet 5
C101  C
C102  C
C103  C
C104  C
C105  C
C106  C
C107  C
C108  C
C109  C
C110  C
C126  C
C127  C
C128  C
C129  C
D19  D
D20  D
IC12  TLP7920(D4ALF1,F
IC13  TLP7920(D4ALF1,F
IC21  TC75S103F
IC22  TC75S103F
IC23  TC75S103F
IC24  TC75S103F
L12  ACT1210-101-2P-TL00
L13  ACT1210-101-2P-TL00
L16  L
L17  L
R102  R
R103  R
R104  R
R105  R
R106  R
R107  R
R108  R
R109  R
R110  R
R111  R
R112  R
R113  R
R114  R
R115  R
R116  R
R117  R
R118  R
R119  R
R120  R
R121  R
R122  R
R123  R
R124  R
R125  R
R126  R
R127  R
R128  R
R129  R
R130  R
R131  R
TP38  TP
TP39  TP
TP40  TP
TP41  TP
U?#3  WAKU_DEF100
sheet 6
C46  C
C47  C
C48  C
C50  C
C51  C
C52  C
C53  C
C54  C
C55  C
C56  C
C57  C
C140  C
C141  C
C142  C
C143  C
C144  C
C146  C
C147  C
C149  C
C150  C
CN8  BM02B-PASS-1-TFT(LF)(SN)
D10  DEW
IC1  REF2025AIDDCT
IC2  TC75S103F
IC28  TC75S103F
IC29  TC75S103F
IC30  TC75S103F
IC31  OPA607IDCKR
IC32  OPA607IDCKR
IC33  OPA607IDCKR
IC34  OPA607IDCKR
IC35  OPA607IDCKR
IC36  OPA607IDCKR
R18  R
R19  R
R20  R
R21  R
R22  R
R23  R
R24  R
R25  R
R26  R
R27  R
R28  R
R29  R
R30  R
R31  R
R32  R
TP10  TP
TP11  TP
TP12  TP
TP13  TP
TP14  TP
TP15  TP
TP62  TP
TP63  TP
TP64  TP
U?#2  WAKU_DEF100
sheet 7
C19  C
C20  MAL216099001E3
C21  C
C22  C
C23  C
C62  C
C63  C
C64  C
C65  C
C70  C
C71  C
C72  C
C73  C
C78  C
C79  C
C80  C
C81  C
C94  C
C95  C
C96  C
C97  C
C98  C
C99  C
C111  C
C112  C
C113  C
C114  C
C115  C
C116  C
C119  C
C120  C
CN1  BM02B-PASS-1-TFT(LF)(SN)
IC4  LP2951D
IC5  LP2951D
IC6  LP2951D
L3  L
LED1  VCDG1111C-4BY3C-TR
LED2  VCDG1111C-4BY3C-TR
PS1  LD20-26B24
PS2  EC5SAW-24S05N
PS3  R24P209D
PS4  R24P209D
PS5  R24P209D
PS6  MEF1S0505SP3C
PS7  MEF1S0505SP3C
R10  R
R11  R
R12  R
R13  R
R43  R
R44  R
R45  R
R56  R
R57  R
R58  R
R69  R
R70  R
R71  R
R144  R
R145  R
TP4  TP
TP5  TP
TP6  TP
TP7  TP
TP8  TP
TP9  TP
TP20  TP
TP25  TP
TP30  TP
TP35  TP
TP37  TP
TP42  TP
TP43  TP
TP52  TP
TP53  TP
TP54  TP
TP55  TP
U?#1  WAKU_DEF100
ZD1  ZD
sheet 8
C117  C
C118  C
CN9  WR-60S-VFH05-N1
IC14  74VHC541FT
IC15  74VHC540FT
R132  R
R133  R
R134  R
R135  R
R136  R
R137  R
R138  R
TP44  TP
TP45  TP
TP46  TP
TP47  TP
TP48  TP
TP49  TP
TP51  TP
U?#8  WAKU_DEF100

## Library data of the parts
C1 C8 C12 C19 C64 C65 C72 C73 C80 C81 C84 C85 C88 C89 C93 C94 C98 C101 C103 C106 C107 C112 C115 C117 C118 C121-C129 = C: COMP: -C-UMK107AB7105KA-T; SIZECODESMD: 1608; VAL1: 1uF(K); VAL2: 50V
C2-C5 C10 C11 = C: COMP: -C-F339X142248MIP2T0; VAL1: 0.22uF(M); VAL2: 480Vac
C6 C7 C9 = C: COMP: -C-F340X153348MPP2T0; VAL1: 3.3uF(M); VAL2: 480Vac
C13-C18 = C: COMP: -C-CD45-E2GA222M-VKA; VAL1: 2200pF(M); VAL2: 440Vac
D1-D3 D17-D20 = D: COMP: -D-BAS316_H3F_AC; USERCOMPTEXT3: TOSHIBA; VAL1: BAS316,H3F; VAL3: BAS316,H3F
F1-F3 = F: COMP: F-0505012.MXEP; VAL1: 0505012.MXEP; VAL3: 0505012.MXEP
L1 L2 = CFA37H_40210R0: COMP: L-CFA37H-40210R0; VAL1: 4mH; VAL2: 10A
PC7 = TLP183: COMP: -PC-TLP183_TPL_E; USERCOMPTEXT3: TOSHIBA
Q7 = SSM3K318R: COMP: -Q-SSM3K318R; INSTANCENAME: INS17447591; SAVECOUNT: 1; UPDATEDATE: 2022/04/12; UPDATETIME: 11:39:41; USERCOMPTEXT3: TOSHIBA
R1 R6 R9 = R: COMP: R-MNG12E740JC; VAL1: 74(J); VAL2: 12W
R2-R5 R7 R8 = R: COMP: -R-RCR60C474J; VAL1: 470k(J); VAL2: 1W
R139 = R: COMP: -R-RK73B2ATTD103J; SIZECODESMD: 2012; VAL1: 10k(J); VAL2: 250mW
R11 R37 R42 R50 R55 R63 R68 R132-R138 R140 = R: COMP: -R-ERJ3EKF1002V; SIZECODESMD: 1608; VAL1: 10k(F); VAL2: 100mW
R141 = R: COMP: -R-ERJ3EKF3900V; SIZECODESMD: 1608; VAL1: 390(F); VAL2: 100mW
R13 R22 R35 R40 R48 R53 R61 R66 R142 = R: COMP: -R-RK73H1JTTD1001F; SIZECODESMD: 1608; VAL1: 1k(F); VAL2: 125mW
R143 = R: COMP: -R-ERJ3EKF3901V; SIZECODESMD: 1608; VAL1: 3.9k(F); VAL2: 100mW
RLY1-RLY3 = G2RL_1A4_E_CF_DC24: COMP: -RLY-G2RL-1A4-E-CF_DC24
TB1-TB4 = OT_264: COMP: -TB-OT-264; INSTANCENAME: INS1928; PART TYPE: Terminal Block; REFERENCE TEMPLATE: TB; SAVECOUNT: 1; SIZE: 1; TYPICAL DIMENSION: 10.0 x 8.0; UPDATEDATE: 2022/04/12; UPDATETIME: 11:39:39
TP1-TP56 TP62-TP64 = TP: COMP: -TP-HK-3-G; VAL1: HK-3-G; VAL3: HK-3-G
U?#7 = WAKU_DEF100: DATE: 2022/06/16; DRAWINGNUMBER: RD207-SCHEMATIC-01; FUNCTION: AC Power In; REVISION: 01; SHEETNUMBER: 1/8; TITLE: 3 Phase AC 400V Input Vienna / Rectifier PFC Converter; UPDATEDATE: 2022/06/16; UPDATETIME: 09:21:32
ZNR1-ZNR3 = VARA: COMP: -ZNR-TND14V-751KB00AAA0; VAL1: TND14V-751KB00AAA0; VAL3: TND14V-751KB00AAA0
C24 C37 C38 C99 C111 C116 = C: COMP: -C-GRM188D71A106KA73D; SIZECODESMD: 1608; VAL1: 10uF(K); VAL2: 10V
C25 C35 C39 C52 C96 C97 C113 C114 = C: COMP: -C-UMK105BJ104KV-F; SIZECODESMD: 1005; VAL1: 0.1uF(K); VAL2: 50V
C26 C28 C30 C36 C40 C44 = C: COMP: -C-CAA572X7T2J105M640LH; SIZECODESMD: 5750; VAL1: 1uF(M); VAL2: 630V
C27 C29 C31 C34 C41 C45 = C: COMP: -C-NC_CAA572X7T2J105M640LH; NOTMOUNT: NOT MOUNT; SIZECODESMD: 5750; VAL1: 1uF(M); VAL2: 630V
C32 C33 C42 C43 = CP: COMP: -C-450MXK470MEFCSN25X55; VAL1: 470uF(M); VAL2: 450V
CN2-CN7 = 6_1460820_1: COMP: CN-6-1460820-1_Micro_SP-NoTH
CT1-CT3 = TMCS1100A2QDR: COMP: -CT-TMCS1100A2QDR
D4 = TRS15N120HB: COMP: D-TRS15N120HB; INSTANCENAME: INS17355299; USERCOMPTEXT3: TOSHIBA
D5 = TRS15N120HB: COMP: D-TRS15N120HB; INSTANCENAME: INS17355445; USERCOMPTEXT3: TOSHIBA
D6 = TRS15N120HB: COMP: D-TRS15N120HB; INSTANCENAME: INS17355424; USERCOMPTEXT3: TOSHIBA
D7 = TRS15N120HB: COMP: D-TRS15N120HB_SP; INSTANCENAME: INS17355299; USERCOMPTEXT3: TOSHIBA
D8 = TRS15N120HB: COMP: D-TRS15N120HB_SP; INSTANCENAME: INS17355424; USERCOMPTEXT3: TOSHIBA
D9 = TRS15N120HB: COMP: D-TRS15N120HB_SP; INSTANCENAME: INS17355445; USERCOMPTEXT3: TOSHIBA
L4-L9 = L: COMP: L-HKBS-24D160-7510; VAL1: 750uH; VAL2: 10A; VAL3: HKBS-24D160-7510
Q1-Q6 = TK065N65Z_S1F: COMP: Q-TK065N65Z_TATE; USERCOMPTEXT3: TOSHIBA
R14-R17 = R: COMP: -R-352239KFT; SIZECODESMD: 6432; VAL1: 39k(F); VAL2: 3W
TB5 TB6 = OT_264: COMP: -TB-OT-264
U?#6 = WAKU_DEF100: DATE: 2022/06/16; DRAWINGNUMBER: RD207-SCHEMATIC-01; FUNCTION: PFC Switching; REVISION: 01; SHEETNUMBER: 2/8; TITLE: 3 Phase AC 400V Input Vienna / Rectifier PFC Converter; UPDATEDATE: 2022/06/16; UPDATETIME: 09:21:32
C58 C60 C66 C68 C74 C76 = C: COMP: C-UMK212B7105KGHT; SIZECODESMD: 2012; VAL1: 1uF(K); VAL2: 50V
C59 C61 C67 C69 C75 C77 = C: COMP: -C-NC_C1608; NOTMOUNT: NOT MOUNT; SIZECODESMD: 1608
D11-D16 = SBD: COMP: -D-CUS10F30_AC; USERCOMPTEXT3: TOSHIBA; VAL1: CUS10F30; VAL3: CUS10F30
PC1-PC6 = TLP5774: COMP: PC-TLP5774H_TP4_E; USERCOMPTEXT3: TOSHIBA; VAL1: TLP5774(TP4,E; VAL3: TLP5774(TP4,E
R33 R38 R46 R51 R59 R64 = R: COMP: -R-RK73H1JTTD6200F; SIZECODESMD: 1608; VAL1: 620(F); VAL2: 125mW
R34 R36 R39 R41 R47 R49 R52 R54 R60 R62 R65 R67 = R: COMP: -R-RK73H2ARTTD10R0F; SIZECODESMD: 2012; VAL1: 100(F); VAL2: 250mW
U?#5 = WAKU_DEF100: DATE: 2022/06/16; DRAWINGNUMBER: RD207-SCHEMATIC-01; FUNCTION: Gate Drive; REVISION: 01; SHEETNUMBER: 3/8; TITLE: 3 Phase AC 400V Input Vienna / Rectifier PFC Converter; UPDATEDATE: 2022/06/16; UPDATETIME: 09:21:32
C86 C91 C102 C105 C108 = C: COMP: -C-GRM1885C1H122JA01J; SIZECODESMD: 1608; VAL1: 1200pF(J); VAL2: 50V
C151-C154 = C: COMP: -C-GCM1885C1H222FA16D; SIZECODESMD: 1608; VAL1: 2200pF(F); VAL2: 50V
IC8 IC9 IC12 IC13 = TLP7920_D4ALF4_F: COMP: IC-TLP7920F_D4ALF4_F; USERCOMPTEXT3: TOSHIBA; VAL1: TLP7920(D4ALF4,F; VAL3: TLP7920(D4ALF4,F
IC2 IC10 IC16-IC24 IC28-IC30 = TC75S103F: COMP: IC-TC75S103F; USERCOMPTEXT3: TOSHIBA
L10-L13 = ACT1210_101_2P_TL00: COMP: -L-ACT1210-101-2P-TL00; VAL1: 100uH(Z); VAL2: 150mA
L14-L17 = L: COMP: L-NC_LQW15CA22NK00D; NOTMOUNT: NOT MOUNT; SIZECODESMD: 1005; VAL1: 22n(K); VAL2: 1.3A; VAL3: LQW15CA22NK00D
R72 R73 R75-R78 R87-R92 R102 R105-R109 R117-R122 = R: COMP: -R-ERA3AEB184V; SIZECODESMD: 1608; VAL1: 180k(B); VAL2: 100mW
R79 R86 R93 R101 R103 R116 R123 R131 = R: COMP: -R-NC_R1005; NOTMOUNT: NOT MOUNT; SIZECODESMD: 1005
R80 R82 R95 R97 = R: COMP: -R-ERA3AEB361V; SIZECODESMD: 1608; VAL1: 360(B); VAL2: 100mW
R81 R83 R96 R98 = R: COMP: -R-ERA3AEB273V; SIZECODESMD: 1608; VAL1: 27k(B); VAL2: 100mW
R10 R12 R84 R99 R114 R129 = R: COMP: -R-RK73Z1JTTD; SIZECODESMD: 1608; VAL1: 0; VAL2: 1A
R146-R149 = R: COMP: -R-ERA3ARB363V; SIZECODESMD: 1608; VAL1: 36k(B); VAL2: 100mW
U?#4 = WAKU_DEF100: DATE: 2022/06/16; DRAWINGNUMBER: RD207-SCHEMATIC-01; FUNCTION: AC Current Detection; REVISION: 01; SHEETNUMBER: 4/8; TITLE: 3 Phase AC 400V Input Vienna / Rectifier PFC Converter; UPDATEDATE: 2022/06/16; UPDATETIME: 09:21:32
C53 C104 C109 = C: COMP: -C-GRM1885C1H102JA01D; SIZECODESMD: 1608; VAL1: 1000pF(J); VAL2: 50V
C110 = C#1: COMP: -C-GRM1885C1H122JA01J; CaptureCellPackProp: C##1; SIZECODESMD: 1608; VAL1: 1200pF(J); VAL2: 50V
R104 R115 R124 = R: COMP: -R-ERA3AEB7152V; SIZECODESMD: 1608; VAL1: 71.5k(B); VAL2: 100mW
R110 R112 R125 R127 = R: COMP: -R-ERA3AEB431V; SIZECODESMD: 1608; VAL1: 430(B); VAL2: 100mW
R18 R23 R25 R26 R30 R32 R111 R113 R126 R128 = R: COMP: -R-ERA3AEB223V; SIZECODESMD: 1608; VAL1: 22k(B); VAL2: 100mW
R130 = R#1: COMP: -R-ERA3AEB7152V; CaptureCellPackProp: R##1; SIZECODESMD: 1608; VAL1: 71.5k(B); VAL2: 100mW
U?#3 = WAKU_DEF100: DATE: 2022/06/16; DRAWINGNUMBER: RD207-SCHEMATIC-01; FUNCTION: DC Voltage Detection; REVISION: 01; SHEETNUMBER: 5/8; UPDATEDATE: 2022/06/16; UPDATETIME: 09:21:32
C46 C47 C54 C57 = C: COMP: -C-GCM1555C1H270FA16D; SIZECODESMD: 1005; VAL1: 27pF(F); VAL2: 50V
C48 C50 C51 C140-C144 C146 C147 C149 C150 = C: COMP: -C-UMK107AB7105KA-T; SIZECODESMD: 1005; VAL1: 1uF(K); VAL2: 50V
C55 C56 = C#1: COMP: -C-GCM1555C1H270FA16D; CaptureCellPackProp: C##1; SIZECODESMD: 1005; VAL1: 27pF(F); VAL2: 50V
CN8 = BM02B_PASS_1_TFT_LF__SN: COMP: -CN-BM02B-PASS-1-TFT_LF_SN
D10 = DEW: COMP: -D-1SS423_TE85L_F_AC; USERCOMPTEXT3: TOSHIBA; VAL1: 1SS423(TE85L,F); VAL3: 1SS423(TE85L,F)
IC1 = REF2025AIDDCT: COMP: -IC-REF2025AIDDCT
IC31-IC36 = OPA607IDCKR: COMP: IC-OPA607IDCKR
R19 R21 R28 R31 = R: COMP: -R-ERA3AEB2942V; SIZECODESMD: 1608; VAL1: 29.4k(B); VAL2: 100mW
R20 = R: COMP: -R-ERJ3EKF2201V; SIZECODESMD: 1608; VAL1: 2.2k(F); VAL2: 100mW
R24 = R: COMP: -R-RK73H1JTTD1003F; SIZECODESMD: 1608; VAL1: 100k(F); VAL2: 100mW
R27 R29 = R#1: COMP: -R-ERA3AEB2942V; CaptureCellPackProp: R##1; SIZECODESMD: 1608; VAL1: 29.4k(B); VAL2: 100mW
U?#2 = WAKU_DEF100: DATE: 2022/06/16; DRAWINGNUMBER: RD207-SCHEMATIC-01; FUNCTION: current detection,Thermal Detection; REVISION: 01; SHEETNUMBER: 6/8; TITLE: 3 Phase AC 400V Input Vienna / Rectifier PFC Converter; UPDATEDATE: 2022/06/16; UPDATETIME: 09:21:33
C20 = MAL216099001E3: COMP: -C-MAL216099001E3; VAL1: 220uF(M); VAL2: 35V
C21-C23 C62 C63 C70 C71 C78 C79 = C: COMP: -C-UMK325AB7106KM-T; SIZECODESMD: 3225; VAL1: 10uF(K); VAL2: 50V
C95 = C: COMP: -C-GRM188D71A106KA73D; SIZECODESMD: 1608; VAL1: 10u(K); VAL2: 10V
C119 C120 = C: COMP: -C-C4532CH3F331K250KA; SIZECODESMD: 4532; VAL1: 330pF(K); VAL2: 3kV
CN1 = B02B-PASK: COMP: -CN-NC_B02B-PASK; NOTMOUNT: NOT MOUNT
IC4-IC6 = LP2951D: COMP: -IC-LP2951D
L3 = L: COMP: -L-MBKK1608T1R0M; SIZECODESMD: 1608; VAL1: 1u(M); VAL2: 1.15A; VAL3: MBKK1608T1R0M
LED1 LED2 = VCDG1111C_4BY3C_TR: COMP: -LED-VCDG1111C-4BY3C-TR_AC; DATE: 2022/04/12; INSTANCENAME: INS17056102; SIZECODESMD: 1608; TIME: 11:39:41; UPDATEDATE: 2022/04/12; UPDATETIME: 11:39:41
PS1 = LD20_26B24: COMP: PS-LD20-26B24
PS2 = EC5SAW_24S05N: COMP: PS-EC5SAW-24S05N
PS3-PS5 = R24P212S: COMP: -PS-R24P212S
PS6 PS7 = MEF1S0505SP3C: COMP: PS-MEF1S0505SP3C
R43 R44 R56 R57 R69 R70 = R: COMP: -R-ERJ3EKF6802V; SIZECODESMD: 1608; VAL1: 68k(B); VAL2: 100mW
R45 R58 R71 = R: COMP: -R-ERJ3EKF1802V; SIZECODESMD: 1608; VAL1: 18k(F); VAL2: 100mW
R144 R145 = R: COMP: -R-NC_R1608; NOTMOUNT: NOT MOUNT; SIZECODESMD: 1608; VAL1: 47k(J); VAL2: 100mW
U?#1 = WAKU_DEF100: DATE: 2022/06/16; DRAWINGNUMBER: RD207-SCHEMATIC-01; FUNCTION: Insulated Power Supply; REVISION: 01; SHEETNUMBER: 7/8; TITLE: 3 Phase AC 400V Input Vienna / Rectifier PFC Converter; UPDATEDATE: 2022/06/16; UPDATETIME: 09:21:33
ZD1 = ZD: COMP: -ZD-SMBJ30A_AC; VAL1: SMBJ30A; VAL3: SMBJ30A
CN9 = WR_60S_VFH05_N1: COMP: -CN-WR-60S-VFH05-N1
IC14 = 74VHC541FT_0: COMP: -IC-74VHCT541AFT; SAVEAREA0: -22847,-24597,51708,30063; SAVECOUNT: 2; UPDATEDATE: 2021/12/27; UPDATETIME: 14:50:23; USERCOMPTEXT3: TOSHIBA; VAL1: 74VHCT541AFT; VAL3: 74VHCT541AFT
IC15 = 74VHC540FT: COMP: -IC-74VHCT540AFT; SAVEAREA0: -22628,-27657,51926,27001; SAVECOUNT: 2; UPDATEDATE: 2021/12/27; UPDATETIME: 14:48:47; USERCOMPTEXT3: TOSHIBA; VAL1: 74VHCT540AFT; VAL3: 74VHCT540AFT
U?#8 = WAKU_DEF100: DATE: 2022/06/16; DRAWINGNUMBER: RD207-SCHEMATIC-01; FUNCTION: Contoroller; REVISION: 01; SHEETNUMBER: 8/8; TITLE: 3 Phase AC 400V Input Vienna / Rectifier PFC Converter; UPDATEDATE: 2022/06/16; UPDATETIME: 09:21:33

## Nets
5V: C23.1 C24.1 C25.1 C35.1 C37.1 C38.1 C39.1 C48.1 C51.1 C85.1 C89.1 C93.1 C97.1 C98.1 C99.1 C101.1 C107.1 C114.1 C115.1 C116.1 C117.1 C118.1 C119.2 C121.1 C122.1 C123.1 C124.1 C125.1 C126.1 C127.1 C128.1 C129.1 C140.1 C141.1 C142.1 C143.1 C144.1 C146.1 C147.1 C149.1 C150.1 CN9.1 CN9.2 CN9.3 CN9.4 CT1.8 CT2.8 CT3.8 D10.C IC1.3(EN) IC1.4(VIN) IC2.5 IC8.8(VDD2) IC9.8(VDD2) IC10.5 IC12.8(VDD2) IC13.8(VDD2) IC14.20(VCC) IC15.20(VCC) IC16.5 IC17.5 IC18.5 IC19.5 IC20.5 IC21.5 IC22.5 IC23.5 IC24.5 IC28.5 IC29.5 IC30.5 IC31.6 IC32.6 IC33.6 IC34.6 IC35.6 IC36.6 PS2.6(+VOUT) PS6.1(VIN) PS7.1(VIN) R13.1 R20.2 R33.1 R38.1 R46.1 R51.1 R59.1 R64.1 R132.2 R133.2 R134.2 R135.2 R136.2 R137.2 R138.2 TP7.1 TP53.1 TP55.1
24V: C1.1 C8.1 C12.1 C19.1 C20.1 C21.1 C62.1 C70.1 C78.1 CN1.1 D1.C D2.C D3.C L3.1 PS3.1(+VIN) PS4.1(+VIN) PS5.1(+VIN) R10.2 R11.1 R139.2 R140.2 RLY1.1 RLY2.1 RLY3.1 TP4.1 TP6.1 ZD1.C
+5V_AC: C84.1 C88.1 C94.1 C95.1 C96.1 D17.C D18.C IC8.1(VDD1) IC9.1(VDD1) PS6.7(+VO) R144.2 TP35.1
+5V_DC: C103.1 C106.1 C111.1 C112.1 C113.1 D19.C D20.C IC12.1(VDD1) IC13.1(VDD1) PS7.7(+VO) R145.2 TP42.1
+10V_U: C58.1 C60.1 C65.1 IC4.1(OUTPUT) PC1.6(Vcc) PC2.6(Vcc) R43.2 TP20.1
+10V_V: C66.1 C68.1 C73.1 IC5.1(OUTPUT) PC3.6(Vcc) PC4.6(Vcc) R56.2 TP25.1
+10V_W: C74.1 C76.1 C81.1 IC6.1(OUTPUT) PC5.6(Vcc) PC6.6(Vcc) R69.2 TP30.1
GND: C23.2 C24.2 C25.2 C35.2 C37.2 C38.2 C39.2 C48.2 C50.2 C51.2 C52.2 C53.2 C85.2 C89.2 C93.2 C97.2 C98.2 C99.2 C101.2 C105.2 C107.2 C108.1 C114.2 C115.2 C116.2 C117.2 C118.2 C120.2 C121.2 C122.2 C123.2 C124.2 C125.2 C126.2 C127.2 C128.2 C129.2 C140.2 C141.2 C142.2 C143.2 C144.2 C146.2 C147.2 C149.2 C150.2 CN8.2 CN9.5 CN9.6 CN9.7 CN9.8 CN9.11 CN9.12 CN9.15 CN9.16 CN9.19 CN9.20 CN9.23 CN9.24 CN9.31 CN9.32 CN9.39 CN9.40 CN9.50 CN9.59 CN9.60 CT1.5 CT2.5 CT3.5 D10.A IC1.2(GND) IC2.2 IC8.5(GND2) IC9.5(GND2) IC10.2 IC12.5(GND2) IC13.5(GND2) IC14.1(OE1) IC14.8(A7) IC14.9(A8) IC14.10(GND) IC14.19(OE2) IC15.1(OE1) IC15.3(A2) IC15.4(A3) IC15.5(A4) IC15.6(A5) IC15.7(A6) IC15.8(A7) IC15.9(A8) IC15.10(GND) IC15.19(OE2) IC16.2 IC17.2 IC18.2 IC19.2 IC20.2 IC21.2 IC22.2 IC23.2 IC24.2 IC28.2 IC29.2 IC30.2 IC31.2 IC32.2 IC33.2 IC34.2 IC35.2 IC36.2 L14.1 L14.2 L15.1 L15.2 L16.1 L16.2 L17.1 L17.2 LED2.C PC7.3(K) PS2.7(-VOUT) PS6.2(GND) PS7.2(GND) R24.1 R115.1 R124.2 R142.1 TP9.1 TP52.1 TP54.1
GND_5Vac: C84.2 C88.2 C94.2 C95.2 C96.2 IC8.4(GND1) IC9.4(GND1) PS6.5(0V) R84.2 R99.2 R144.1 TP37.1
GND_5Vdc: C103.2 C106.2 C111.2 C112.2 C113.2 IC12.4(GND1) IC13.4(GND1) PS7.5(0V) R114.2 R129.2 R145.1 TP43.1
GND_24V: C1.2 C8.2 C12.2 C19.2 C20.2 C21.2 C22.2 C62.2 C70.2 C78.2 C120.1 CN1.2 LED1.C PS2.1(-VIN) PS3.2(-VIN) PS4.2(-VIN) PS5.2(-VIN) Q7.S R12.2 R143.1 TP5.1 TP8.1 ZD1.A
GND_U: C58.2 C59.2 C60.2 C61.2 C63.2 C64.2 C65.2 CN2.G1 CN2.G2 CN3.G1 CN3.G2 IC4.3(SHUTDOWN) IC4.4(GND) PC1.4(GND) PC2.4(GND) PS3.5(-VOUT) Q1.S Q2.S R37.1 R42.1 R45.1 TP17.1 TP19.1
GND_V: C66.2 C67.2 C68.2 C69.2 C71.2 C72.2 C73.2 CN4.G1 CN4.G2 CN5.G1 CN5.G2 IC5.3(SHUTDOWN) IC5.4(GND) PC3.4(GND) PC4.4(GND) PS4.5(-VOUT) Q3.S Q4.S R50.1 R55.1 R58.1 TP22.1 TP24.1
GND_W: C74.2 C75.2 C76.2 C77.2 C79.2 C80.2 C81.2 CN6.G1 CN6.G2 CN7.G1 CN7.G2 IC6.3(SHUTDOWN) IC6.4(GND) PC5.4(GND) PC6.4(GND) PS5.5(-VOUT) Q5.S Q6.S R63.1 R68.1 R71.1 TP27.1 TP29.1
/DO1_BI: CN9.42 IC15.2(A1) R138.1
/MainRLY_24V: D1.A D2.A D3.A Q7.D R139.1 RLY1.8 RLY2.8 RLY3.8 TP50.1
/PWM1A_BI: CN9.25 IC14.2(A1) R132.1
/PWM1B_BI: CN9.26 IC14.3(A2) R133.1
/PWM2A_BI: CN9.27 IC14.4(A3) R134.1
/PWM2B_BI: CN9.28 IC14.5(A4) R135.1
/PWM3A_BI: CN9.29 IC14.6(A5) R136.1
/PWM3B_BI: CN9.30 IC14.7(A6) R137.1
/PWM_U_A: IC14.18(Y1) PC1.3(K) R35.2 TP44.1
/PWM_U_B: IC14.17(Y2) PC2.3(K) R40.2 TP45.1
/PWM_V_A: IC14.16(Y3) PC3.3(K) R48.2 TP46.1
/PWM_V_B: IC14.15(Y4) PC4.3(K) R53.2 TP47.1
/PWM_W_A: IC14.14(Y5) PC5.3(K) R61.2 TP48.1
/PWM_W_B: IC14.13(Y6) PC6.3(K) R66.2 TP49.1
AC_L_IN_W: L2.6 PS1.3(AC(L)) R9.2 RLY3.4 RLY3.5
AC_N_IN: L2.4 PS1.2(AC(N)) R6.2 RLY2.4 RLY2.5
AC_U: C6.1 C7.1 CT1.3 CT1.4 R1.1 R75.1 RLY1.3 RLY1.6 TP1.1
AC_V: C6.2 C9.1 C86.2 C91.2 CT2.3 CT2.4 L10.2 L11.2 R6.1 R80.1 R86.1 R95.1 R101.1 RLY2.3 RLY2.6 TP2.1
AC_W: C7.2 C9.2 CT3.3 CT3.4 R9.1 R87.1 RLY3.3 RLY3.6 TP3.1
AD0: CN9.9 IC16.1 IC16.4 TP31.1
AD1: CN9.10 IC18.1 IC18.4 TP34.1
AD2: CN9.13 IC21.1 IC21.4 TP38.1
AD3: CN9.14 IC23.1 IC23.4 TP41.1
AD4: CN9.17 IC31.3 IC31.4 TP13.1
AD5: CN9.18 IC33.3 IC33.4 TP14.1
AD6: CN9.21 IC35.3 IC35.4 TP15.1
AD7: CN9.22 IC2.1 IC2.4 TP10.1
FG: C13.2 C14.2 C15.2 C16.2 C17.2 C18.2 TB4.1 TB4.2
Gate_U_A: C59.1 CN2.S D11.A Q1.G R36.2 R37.2 TP16.1
Gate_U_B: C61.1 CN3.S D12.A Q2.G R41.2 R42.2 TP18.1
Gate_V_A: C67.1 CN4.S D13.A Q3.G R49.2 R50.2 TP21.1
Gate_V_B: C69.1 CN5.S D14.A Q4.G R54.2 R55.2 TP23.1
Gate_W_A: C75.1 CN6.S D15.A Q5.G R62.2 R63.2 TP26.1
Gate_W_B: C77.1 CN7.S D16.A Q6.G R67.2 R68.2 TP28.1
lu: CT1.7 R23.1
lv: CT2.7 R25.1
lw: CT3.7 R26.2
SIG001: IC15.18(Y1) R141.1 TP51.1
SIG39: LED2.A R13.2
SIG40: C22.1 C119.1 L3.2 PS2.2(+VIN)
SIG52: C79.1 C80.1 IC6.8(INPUT) PS5.7(+VOUT)
SIG55: R69.1 R70.1
SIG75: IC6.7(FEEDBACK) R70.2 R71.2
SIG89: LED1.A R11.2
SIG93: PS1.4(+Vo) R10.1
SIG94: PS1.8(-Vo) R12.1
SIG101: C47.2 IC32.1 R21.1 R23.2
SIG106: C46.2 IC31.1 IC32.4 R19.1
SIG113: C57.2 IC33.1 IC34.4 R31.1
SIG115: C57.1 IC34.3 R30.2 R31.2
SIG122: C54.2 IC34.1 R25.2 R28.1
SIG129: C56.1(2) IC35.1 IC36.4 R29.2(1)
SIG131: C56.2(1) IC36.3 R29.1(2) R32.2
SIG138: C55.1(2) IC36.1 R26.1 R27.2(1)
SIG144: IC1.1(VBIAS) TP12.1
SIG155: D17.A IC8.2(VIN+) L10.4 R79.2 TP32.1
SIG166: C86.1 L10.1 R77.2 R79.1 R80.2
SIG168: IC8.3(VIN-) R82.2
SIG169: L10.3 R82.1 R84.1 R86.2
SIG171: IC8.7(VOUT+) R81.1
SIG172: IC8.6(VOUT-) R83.1
SIG174: C151.1 IC17.3 R81.2 R146.2
SIG181: C152.1 IC16.3 IC17.1 R147.2
SIG182: C152.2 IC17.4 R83.2 R147.1
SIG186: C151.2 IC10.1 IC10.4 R146.1 TP36.1
SIG189: L11.3 R97.1 R99.1 R101.2
SIG190: C91.1 L11.1 R92.2 R93.1 R95.2
SIG200: C154.1 IC18.3 IC19.1 R149.2
SIG201: C154.2 IC19.4 R98.2 R149.1
SIG204: C153.1 IC19.3 R96.2 R148.2
SIG207: D18.A IC9.2(VIN+) L11.4 R93.2 TP33.1
SIG213: IC9.7(VOUT+) R96.1
SIG215: IC9.6(VOUT-) R98.1
SIG218: C153.2 IC20.1 IC20.4 R148.1 TP56.1
SIG219: IC9.3(VIN-) R97.2
SIG220: L12.3 R112.2 R114.1 R116.2
SIG221: L13.3 R127.2 R129.1 R131.2
SIG226: C109.1 L13.1 R122.2 R123.1 R125.2
SIG227: C104.1 L12.1 R103.1 R107.2 R110.2
SIG235: C102.1 IC21.3 IC22.1 R104.2
SIG236: IC13.3(VIN-) R127.1
SIG237: C102.2 IC22.4 R104.1 R113.2
SIG239: C105.1 IC22.3 R111.2 R115.2
SIG241: D19.A IC12.2(VIN+) L12.4 R103.2 TP39.1
SIG246: IC13.6(VOUT-) R128.1
SIG247: IC13.7(VOUT+) R126.1
SIG251: IC12.7(VOUT+) R111.1
SIG253: IC12.6(VOUT-) R113.1
SIG254: D20.A IC13.2(VIN+) L13.4 R123.2 TP40.1
SIG255: C110.2(1) IC23.3 IC24.1 R130.1(2)
SIG263: C108.2 IC24.3 R124.1 R128.2
SIG265: IC12.3(VIN-) R112.1
SIG271: C52.1 CN8.1 R20.1 R22.2 R24.2
SIG275: C53.1 D10.C/A(AC) IC2.3 R22.1
SIG282: PC1.1(A) R33.2 R35.1
SIG284: PC1.5(Vo) R34.1 R36.1
SIG285: D11.C R34.2
SIG289: PC2.5(Vo) R39.1 R41.1
SIG291: D12.C R39.2
SIG292: PC2.1(A) R38.2 R40.1
SIG294: PC3.5(Vo) R47.1 R49.1
SIG295: D13.C R47.2
SIG296: PC3.1(A) R46.2 R48.1
SIG298: PC5.5(Vo) R60.1 R62.1
SIG299: D15.C R60.2
SIG300: PC5.1(A) R59.2 R61.1
SIG304: PC4.1(A) R51.2 R53.1
SIG305: PC4.5(Vo) R52.1 R54.1
SIG306: D14.C R52.2
SIG308: PC6.1(A) R64.2 R66.1
SIG309: PC6.5(Vo) R65.1 R67.1
SIG310: D16.C R65.2
SIG317: CT3.1 CT3.2 L8.1
SIG318: L8.2 L9.1
SIG322: L4.2 L5.1
SIG325: CT1.1 CT1.2 L4.1
SIG329: L6.2 L7.1
SIG330: CT2.1 CT2.2 L6.1
SIG332: D6.1(A) D6.3(A) D8.2(C) L9.2 Q5.D
SIG333: D5.1(A) D5.3(A) D9.2(C) L7.2 Q3.D
SIG334: R16.1 R17.2
SIG335: R14.1 R15.2
SIG337: D4.1(A) D4.3(A) D7.2(C) L5.2 Q1.D
SIG338: F3.1 TB3.1 TB3.2
SIG339: F2.1 TB2.1 TB2.2
SIG340: F1.1 TB1.1 TB1.2
SIG341: C2.2 C10.1 C14.1 F2.2 L1.3 R2.1 R8.2 ZNR1.1 ZNR3.2
SIG342: C3.2 C10.2 C15.1 F3.2 L1.5 R3.1 R8.1 ZNR2.1 ZNR3.1
SIG343: C2.1 C3.1 C13.1 F1.2 L1.1 R2.2 R3.2 ZNR1.2 ZNR2.2
SIG344: C4.1 C5.1 C16.1 L1.2 L2.1 R4.2 R5.2
SIG345: C4.2 C11.1 C17.1 L1.4 L2.3 R4.1 R7.2
SIG346: C5.2 C11.2 C18.1 L1.6 L2.5 R5.1 R7.1
SIG356: L2.2 R1.2 RLY1.4 RLY1.5
SIG366: PC7.1(A) R141.2 R142.2
SIG369: PC7.6(C) R140.1
SIG371: PC7.4(E) Q7.G R143.2
SIG376: C46.1 IC32.3 R18.2 R19.2
SIG377: C110.1(2) IC24.4 R126.2 R130.2(1)
SIG378: IC5.7(FEEDBACK) R57.2 R58.2
SIG381: C71.1 C72.1 IC5.8(INPUT) PS4.7(+VOUT)
SIG382: R56.1 R57.1
SIG383: IC4.7(FEEDBACK) R44.2 R45.2
SIG386: C63.1 C64.1 IC4.8(INPUT) PS3.7(+VOUT)
SIG387: R43.1 R44.1
Vdc_M: C26.2 C27.2 C28.2 C29.2 C30.2 C31.2 C32.2(1) C33.2(1) C34.1 C36.1 C40.1 C41.1 C42.1(2) C43.1(2) C44.1 C45.1 C104.2 C109.2 L12.2 L13.2 Q2.D Q4.D Q6.D R15.1 R16.2 R110.1 R116.1 R125.1 R131.1
Vdc_N: C34.2 C36.2 C40.2 C41.2 C42.2(1) C43.2(1) C44.2 C45.2 D7.1(A) D7.3(A) D8.1(A) D8.3(A) D9.1(A) D9.3(A) R17.1 R117.1 TB6.1 TB6.2
Vdc_P: C26.1 C27.1 C28.1 C29.1 C30.1 C31.1 C32.1(2) C33.1(2) D4.2(C) D5.2(C) D6.2(C) R14.2 R105.1 TB5.1 TB5.2
Vref: C50.1 IC1.5(VREF) IC10.3 IC20.3 IC28.3 IC29.3 IC30.3 TP11.1
Vref_in_u: C47.1 CT1.6 IC28.1 IC28.4 R18.1 R21.2 TP62.1
Vref_in_v: C54.1 CT2.6 IC29.1 IC29.4 R28.2 R30.1 TP63.1
Vref_in_w: C55.2(1) CT3.6 IC30.1 IC30.4 R27.1(2) R32.1 TP64.1
N07397: R87.2 R88.1
N07398: R90.2 R91.1
N07401: R89.2 R90.1
N07402: R77.1 R78.2
N07405: R72.2 R76.1
N07406: R73.1 R76.2
N07407: R88.2 R89.1
N07408: R73.2 R78.1
N07409: R72.1 R75.2
N07410: R91.2 R92.1
N09148: R121.2 R122.1
N09149: R102.2 R108.1
N09150: R120.2 R121.1
N09151: R107.1 R109.2
N09153: R106.1 R108.2
N09154: R106.2 R109.1
N09155: R118.2 R119.1
N09156: R119.2 R120.1
N09157: R117.2 R118.1
N09158: R102.1 R105.2

Not connected (* = marked no-connect by the designer): C20 NC1 NC2; CN8 NC1 NC2; CN9 33 34 35 36 37 38 41 43 44 45 46 47 48 49 51 52 53 54 55 56 57 58; IC4 2(SENSE) 5(ERROR) 6(VTAP); IC5 2(SENSE) 5(ERROR) 6(VTAP); IC6 2(SENSE) 5(ERROR) 6(VTAP); IC14 11(Y8) 12(Y7); IC15 11(Y8) 12(Y7) 13(Y6) 14(Y5) 15(Y4) 16(Y3) 17(Y2); IC31 5; IC32 5; IC33 5; IC34 5; IC35 5; IC36 5; PC1 2(NC); PC2 2(NC); PC3 2(NC); PC4 2(NC); PC5 2(NC); PC6 2(NC); PS2 3(On/Off) 8(NC)

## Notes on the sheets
sheet 3
- Fc = 200.5kHz
- Fc = 200.5kHz
- Fc = 200.5kHz
- THERMISTOR
- EC2F103A2-40113
sheet 4
- Fc = 370kHz
- Fc = 370kHz
sheet 5
- Fc = 370kHz
- Fc = 370kHz
